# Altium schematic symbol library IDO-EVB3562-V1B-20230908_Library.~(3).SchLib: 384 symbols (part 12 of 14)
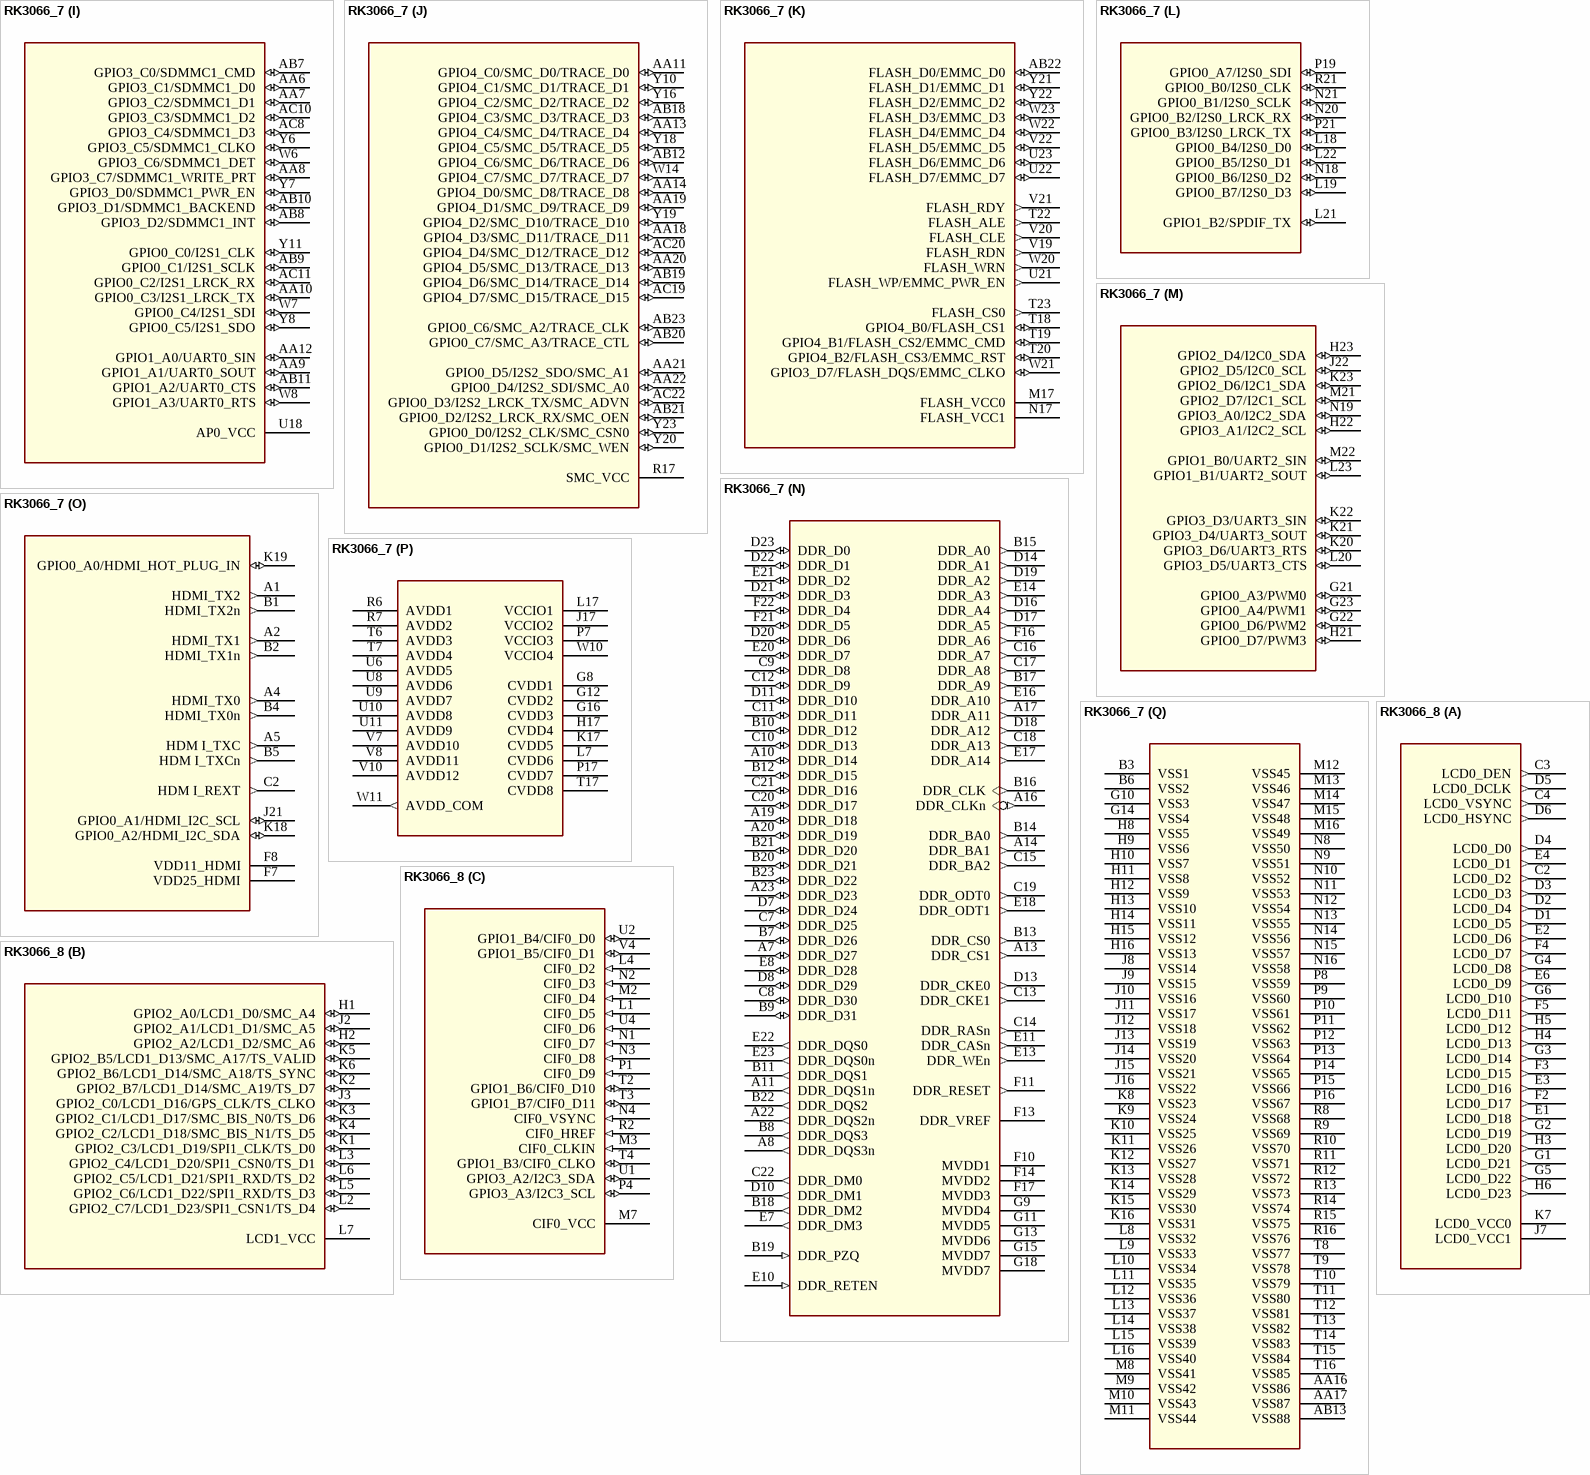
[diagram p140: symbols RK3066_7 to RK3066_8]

## RK3066_7
designator U?
Altium-Right: 160; Altium-Bottom: 130; Altium-Bottom1: 280; Altium-Right2: 180; Altium-Bottom2: 310; Altium-Bottom3: 270; Altium-Right4: 120; Altium-Bottom4: 140; Altium-Bottom5: 230; Altium-Bottom6: 530; Altium-Right7: 150; Altium-Bottom7: 250; Altium-Right8: 110; Altium-Bottom8: 170; Altium-Right9: 100; Altium-Bottom9: 470; Altium-Right10: 80; Altium-Bottom10: 350; Altium-Right11: 200; Altium-Bottom11: 190
footprint BGA453
part A pins: C3 LCD0_DEN (out), C4 LCD0_DCLK (out), C5 LCD0_VSYNC (out), C6 LCD0_HSYNC (out), D1 LCD0_D6 (out), D2 LCD0_D5 (out), D3 LCD0_D4 (out), D4 LCD0_D3 (out), D5 LCD0_D2 (out), D6 LCD0_D1 (out), E1 LCD0_D10 (out), E2 LCD0_D7 (out), E3 LCD0_D9 (out), E4 LCD0_D8 (out), E6 LCD0_D0 (out), F2 LCD0_D13 (out), F3 LCD0_D12 (out), F4 LCD0_D14 (out), F5 LCD0_D11 (out), G1 LCD0_D20 (out), G2 LCD0_D19 (out), G3 LCD0_D18 (out), G4 LCD0_D17 (out), G5 LCD0_D16 (out), G6 LCD0_D15 (out), H1 LCD0_D21 (out), H5 LCD0_D22 (out), H6 LCD0_D23 (out), H7 LCD0_VCC1 (power), J7 LCD0_VCC0 (power)
part B pins: H2 GPIO2_A0/LCD1_D0/SMC_A4 (io), H3 GPIO2_A1/LCD1_D1/SMC_A5 (io), H4 GPIO2_A2/LCD1_D2/SMC_A6 (io), J2 GPIO2_B7/LCD1_D14/SMC_A19/TS_D7 (io), J3 GPIO2_B6/LCD1_D14/SMC_A18/TS_SYNC (io), K1 GPIO2_C2/LCD1_D18/SMC_BIS_N1/TS_D5 (io), K2 GPIO2_C1/LCD1_D17/SMC_BIS_N0/TS_D6 (io), K3 GPIO2_B5/LCD1_D13/SMC_A17/TS_VALID (io), K4 GPIO2_C0/LCD1_D16/GPS_CLK/TS_CLKO (io), K7 LCD1_VCC (power), L1 GPIO2_C5/LCD1_D21/SPI1_RXD/TS_D2 (io), L2 GPIO2_C4/LCD1_D20/SPI1_CSN0/TS_D1 (io), L3 GPIO2_C3/LCD1_D19/SPI1_CLK/TS_D0 (io), L4 GPIO2_C7/LCD1_D23/SPI1_CSN1/TS_D4 (io), M2 GPIO2_C6/LCD1_D22/SPI1_RXD/TS_D3 (io)
part C pins: K5 CIF0_D5 (in), K6 CIF0_D2 (in), L5 CIF0_D9 (in), L6 CIF0_CLKIN (in), M3 CIF0_D8 (in), M7 CIF0_VCC (power), N1 CIF0_D4 (in), N2 CIF0_D3 (in), N3 CIF0_D7 (in), N4 GPIO1_B4/CIF0_D0 (io), N5 GPIO1_B3/CIF0_CLKO (io), N6 GPIO1_B5/CIF0_D1 (io), P1 CIF0_D6 (in), P2 CIF0_VSYNC (in), P3 CIF0_HREF (in), P4 GPIO1_B6/CIF0_D10 (io), P5 GPIO3_A3/I2C3_SCL (io), R2 GPIO3_A2/I2C3_SDA (io), R3 GPIO1_B7/CIF0_D11 (io)
part D pins: N7 CIF1_VCC (power), T1 GPIO1_C5/CIF1_D7/RMII_CRS_DVALID (io), T2 GPIO1_C0/CIF1_D2/RMII_CLKO (io), T3 GPIO1_C2/CIF1_D4/RMII_TXD1 (io), T4 GPIO1_C1/CIF1_D3/RMII_TX_EN (io), T5 GPIO1_C7/CIF1_D9/RMII_RXD0 (io), U1 GPIO1_D2/CIF1_CLKIN (io), U2 GPIO1_C4/CIF1_D6/RMII_RX_ERR (io), U3 GPIO1_C3/CIF1_D5/RMII_TXD0 (io), U4 GPIO1_D0/CIF1_VSYNC/MII_MD (io), U5 GPIO3_A5/I2C4_SCL (io), V2 GPIO1_D7/CIF1_CLKO (io), V3 GPIO1_C6/CIF1_D8/RMII_RXD1 (io), V4 GPIO1_D1/CIF1_HREF/MII_MDCLK (io), V5 GPIO3_A4/I2C4_SDA (io), W4 GPIO1_D6/CIF1_D11 (io)
part E pins: AA2 GPIO6_A4, AA3 GPIO6_A5, AA15 PVCC_3V3 (power), AB1 GPIO6_B0, AB2 GPIO6_B1, AB3 GPIO6_A1, AB4 GPIO6_A7, AB14 XOUT24M (out), AC1 GPIO6_A0, AC2 GPIO6_A3, AC4 GPIO6_A2, AC5 GPIO6_A6, AC13 DDRIO_RET_EN (out), AC14 XIN24M (in), U12 AVSS_APLL (power), U13 AVSS_DPLL (power), U14 AVSS_C/GPLL (power), V11 APLL_1V1 (power), V13 DPLL_1V1 (power), V14 C/GPLL_1V1 (power), V17 EFUSE (in), W13 PVDD_1V1 (power), Y1 CPU_PWROFF (out), Y2 CORE_PWROFF (out), Y3 DDRIO_PWROFF (out), Y4 GPIO6_B2, Y5 GPIO6_B3, Y13 CLKIN_32K (in), Y14 NPOR (in)
part F pins: AB15 HOST_RKELVIN (out), AB16 OTG_DM (io), AB17 HOST_DM (io), AC16 OTG_DP (io), AC17 HOST_DP (io), F19 GPIO0_A6/HOST_DRV (io), F20 TDO (out), G19 TDI/CPR_BYPASS (in), G20 TRSTN (in), H18 TCK/HSSCAN_SHIFT_CLOCK (in), H19 TMS/PLL_BYPASS (io), H20 RECOVER (in), P20 GPIO0_A5/OTG_DRV (io), U15 USBVDD_1V1 (power), U16 USBVDD_2V5 (power), V16 USBVDD_3V3 (power), W1 SARADC_ANI0 (in), W2 SARADC_ANI2 (in), W3 SARADC_ANI1 (in), W16 OTG_RKELVIN (out), W17 OTG_VBUS (in), Y17 OTG_ID (in)
part G pins: AA4 GPIO1_A4/UART1_RX/SPI0_CSN0 (io), AA5 GPIO4_B7/SPI0_CSN1 (io), AB5 GPIO1_A5/UART1_TX/SPI0_CLK (io), AB6 GPIO1_A6/UART1_CTSN/SPI0_RXD (io), AC7 GPIO1_A7/UART1_RTSN/SPI0_TXD (io), W18 AP1_VCC (power)
part H pins: AC23 GPIO3_B6/SDMMC0_DET (io), N22 GPIO3_B4/SDMMC0_D2 (io), N23 GPIO3_B5/SDMMC0_D3 (io), P18 GPIO3_A6/SDMMC0_RSTNO (io), P22 GPIO3_B3/SDMMC0_D1 (io), P23 GPIO3_B7/SDMMC0_WRITE_PRT (io), R22 GPIO3_A7/SDMMC0_PWR_EN (io), T21 GPIO3_B0/SDMMC0_CLKOUT (io), U19 GPIO3_B2/SDMMC0_D0 (io), U20 GPIO3_B1/SDMMC0_CMD (io)
part I pins: AA6 GPIO3_C1/SDMMC1_D0 (io), AA7 GPIO3_C2/SDMMC1_D1 (io), AA8 GPIO3_C7/SDMMC1_WRITE_PRT (io), AA9 GPIO1_A1/UART0_SOUT (io), AA10 GPIO0_C3/I2S1_LRCK_TX (io), AA12 GPIO1_A0/UART0_SIN (io), AB7 GPIO3_C0/SDMMC1_CMD (io), AB8 GPIO3_D2/SDMMC1_INT (io), AB9 GPIO0_C1/I2S1_SCLK (io), AB10 GPIO3_D1/SDMMC1_BACKEND (io), AB11 GPIO1_A2/UART0_CTS (io), AC8 GPIO3_C4/SDMMC1_D3 (io), AC10 GPIO3_C3/SDMMC1_D2 (io), AC11 GPIO0_C2/I2S1_LRCK_RX (io), U18 AP0_VCC (power), W6 GPIO3_C6/SDMMC1_DET (io), W7 GPIO0_C4/I2S1_SDI (io), W8 GPIO1_A3/UART0_RTS (io), Y6 GPIO3_C5/SDMMC1_CLKO (io), Y7 GPIO3_D0/SDMMC1_PWR_EN (io), Y8 GPIO0_C5/I2S1_SDO (io), Y11 GPIO0_C0/I2S1_CLK (io)
part J pins: AA11 GPIO4_C0/SMC_D0/TRACE_D0 (io), AA13 GPIO4_C4/SMC_D4/TRACE_D4 (io), AA14 GPIO4_D0/SMC_D8/TRACE_D8 (io), AA18 GPIO4_D3/SMC_D11/TRACE_D11 (io), AA19 GPIO4_D1/SMC_D9/TRACE_D9 (io), AA20 GPIO4_D5/SMC_D13/TRACE_D13 (io), AA21 GPIO0_D5/I2S2_SDO/SMC_A1 (io), AA22 GPIO0_D4/I2S2_SDI/SMC_A0 (io), AB12 GPIO4_C6/SMC_D6/TRACE_D6 (io), AB18 GPIO4_C3/SMC_D3/TRACE_D3 (io), AB19 GPIO4_D6/SMC_D14/TRACE_D14 (io), AB20 GPIO0_C7/SMC_A3/TRACE_CTL (io), AB21 GPIO0_D2/I2S2_LRCK_RX/SMC_OEN (io), AB23 GPIO0_C6/SMC_A2/TRACE_CLK (io), AC19 GPIO4_D7/SMC_D15/TRACE_D15 (io), AC20 GPIO4_D4/SMC_D12/TRACE_D12 (io), AC22 GPIO0_D3/I2S2_LRCK_TX/SMC_ADVN (io), R17 SMC_VCC (power), W14 GPIO4_C7/SMC_D7/TRACE_D7 (io), Y10 GPIO4_C1/SMC_D1/TRACE_D1 (io), Y16 GPIO4_C2/SMC_D2/TRACE_D2 (io), Y18 GPIO4_C5/SMC_D5/TRACE_D5 (io), Y19 GPIO4_D2/SMC_D10/TRACE_D10 (io), Y20 GPIO0_D1/I2S2_SCLK/SMC_WEN (io), Y23 GPIO0_D0/I2S2_CLK/SMC_CSN0 (io)
part K pins: AB22 FLASH_D0/EMMC_D0 (io), M17 FLASH_VCC0 (power), N17 FLASH_VCC1 (power), T18 GPIO4_B0/FLASH_CS1 (io), T19 GPIO4_B1/FLASH_CS2/EMMC_CMD (io), T20 GPIO4_B2/FLASH_CS3/EMMC_RST (io), T22 FLASH_ALE (out), T23 FLASH_CS0 (out), U21 FLASH_WP/EMMC_PWR_EN (out), U22 FLASH_D7/EMMC_D7 (io), U23 FLASH_D6/EMMC_D6 (io), V19 FLASH_RDN (out), V20 FLASH_CLE (out), V21 FLASH_RDY (out), V22 FLASH_D5/EMMC_D5 (io), W20 FLASH_WRN (out), W21 GPIO3_D7/FLASH_DQS/EMMC_CLKO (io), W22 FLASH_D4/EMMC_D4 (io), W23 FLASH_D3/EMMC_D3 (io), Y21 FLASH_D1/EMMC_D1 (io), Y22 FLASH_D2/EMMC_D2 (io)
part L pins: L18 GPIO0_B4/I2S0_D0 (io), L19 GPIO0_B7/I2S0_D3 (io), L21 GPIO1_B2/SPDIF_TX (io), L22 GPIO0_B5/I2S0_D1 (io), N18 GPIO0_B6/I2S0_D2 (io), N20 GPIO0_B2/I2S0_LRCK_RX (io), N21 GPIO0_B1/I2S0_SCLK (io), P19 GPIO0_A7/I2S0_SDI (io), P21 GPIO0_B3/I2S0_LRCK_TX (io), R21 GPIO0_B0/I2S0_CLK (io)
part M pins: G21 GPIO0_A3/PWM0 (io), G22 GPIO0_D6/PWM2 (io), G23 GPIO0_A4/PWM1 (io), H21 GPIO0_D7/PWM3 (io), H22 GPIO3_A1/I2C2_SCL (io), H23 GPIO2_D4/I2C0_SDA (io), J22 GPIO2_D5/I2C0_SCL (io), K20 GPIO3_D6/UART3_RTS (io), K21 GPIO3_D4/UART3_SOUT (io), K22 GPIO3_D3/UART3_SIN (io), K23 GPIO2_D6/I2C1_SDA (io), L20 GPIO3_D5/UART3_CTS (io), L23 GPIO1_B1/UART2_SOUT (io), M21 GPIO2_D7/I2C1_SCL (io), M22 GPIO1_B0/UART2_SIN (io), N19 GPIO3_A0/I2C2_SDA (io)
part N pins: A7 DDR_D27 (io), A8 DDR_DQS3n (out), A10 DDR_D14 (io), A11 DDR_DQS1n (out), A13 DDR_CS1 (out), A14 DDR_BA1 (out), A16 DDR_CLKn (out), A17 DDR_A11 (out), A19 DDR_D18 (io), A20 DDR_D19 (io), A22 DDR_DQS2n (out), A23 DDR_D23 (io), B7 DDR_D26 (io), B8 DDR_DQS3 (out), B9 DDR_D31 (io), B10 DDR_D12 (io), B11 DDR_DQS1 (out), B12 DDR_D15 (io), B13 DDR_CS0 (out), B14 DDR_BA0 (out), B15 DDR_A0 (out), B16 DDR_CLK (out), B17 DDR_A9 (out), B18 DDR_DM2 (out), B19 DDR_PZQ (in), B20 DDR_D21 (io), B21 DDR_D20 (io), B22 DDR_DQS2 (out), B23 DDR_D22 (io), C7 DDR_D25 (io), C8 DDR_D30 (io), C9 DDR_D8 (io), C10 DDR_D13 (io), C11 DDR_D11 (io), C12 DDR_D9 (io), C13 DDR_CKE1 (out), C14 DDR_RASn (out), C15 DDR_BA2 (out), C16 DDR_A7 (out), C17 DDR_A8 (out), C18 DDR_A13 (out), C19 DDR_ODT0 (out), C20 DDR_D17 (io), C21 DDR_D16 (io), C22 DDR_DM0 (out), D7 DDR_D24 (io), D8 DDR_D29 (io), D10 DDR_DM1 (out), D11 DDR_D10 (io), D13 DDR_CKE0 (out), D14 DDR_A1 (out), D16 DDR_A4 (out), D17 DDR_A5 (out), D18 DDR_A12 (out), D19 DDR_A2 (out), D20 DDR_D6 (io), D21 DDR_D3 (io), D22 DDR_D1 (io), D23 DDR_D0 (io), E7 DDR_DM3 (out), E8 DDR_D28 (io), E10 DDR_RETEN (in), E11 DDR_CASn (out), E13 DDR_WEn (out), E14 DDR_A3 (out), E16 DDR_A10 (out), E17 DDR_A14 (out), E18 DDR_ODT1 (out), E20 DDR_D7 (io), E21 DDR_D2 (io), E22 DDR_DQS0 (out), E23 DDR_DQS0n (out), F10 MVDD1 (power), F11 DDR_RESET (out), F13 DDR_VREF (power), F14 MVDD2 (power), F16 DDR_A6 (out), F17 MVDD3 (power), F21 DDR_D5 (io), F22 DDR_D4 (io), G9 MVDD4 (power), G11 MVDD5 (power), G13 MVDD6 (power), G15 MVDD7 (power), G18 MVDD7 (power)
part O pins: A1 HDMI_TX2 (out), A2 HDMI_TX1 (out), A4 HDMI_TX0 (out), A5 HDM I_TXC (out), B1 HDMI_TX2n (out), B2 HDMI_TX1n (out), B4 HDMI_TX0n (out), B5 HDM I_TXCn (out), C2 HDM I_REXT (out), F7 VDD25_HDMI (power), F8 VDD11_HDMI (power), J21 GPIO0_A1/HDMI_I2C_SCL (io), K18 GPIO0_A2/HDMI_I2C_SDA (io), K19 GPIO0_A0/HDMI_HOT_PLUG_IN (io)
part P pins: G8 CVDD1 (power), G12 CVDD2 (power), G16 CVDD3 (power), H17 CVDD4 (power), J17 VCCIO2 (power), K17 CVDD5 (power), L7 CVDD6 (power), L17 VCCIO1 (power), P7 VCCIO3 (power), P17 CVDD7 (power), R6 AVDD1 (power), R7 AVDD2 (power), T6 AVDD3 (power), T7 AVDD4 (power), T17 CVDD8 (power), U6 AVDD5 (power), U8 AVDD6 (power), U9 AVDD7 (power), U10 AVDD8 (power), U11 AVDD9 (power), V7 AVDD10 (power), V8 AVDD11 (power), V10 AVDD12 (power), W10 VCCIO4 (power), W11 AVDD_COM (out)
part Q pins: AA16 VSS86 (power), AA17 VSS87 (power), AB13 VSS88 (power), B3 VSS1 (power), B6 VSS2 (power), G10 VSS3 (power), G14 VSS4 (power), H8 VSS5 (power), H9 VSS6 (power), H10 VSS7 (power), H11 VSS8 (power), H12 VSS9 (power), H13 VSS10 (power), H14 VSS11 (power), H15 VSS12 (power), H16 VSS13 (power), J8 VSS14 (power), J9 VSS15 (power), J10 VSS16 (power), J11 VSS17 (power), J12 VSS18 (power), J13 VSS19 (power), J14 VSS20 (power), J15 VSS21 (power), J16 VSS22 (power), K8 VSS23 (power), K9 VSS24 (power), K10 VSS25 (power), K11 VSS26 (power), K12 VSS27 (power), K13 VSS28 (power), K14 VSS29 (power), K15 VSS30 (power), K16 VSS31 (power), L8 VSS32 (power), L9 VSS33 (power), L10 VSS34 (power), L11 VSS35 (power), L12 VSS36 (power), L13 VSS37 (power), L14 VSS38 (power), L15 VSS39 (power), L16 VSS40 (power), M8 VSS41 (power), M9 VSS42 (power), M10 VSS43 (power), M11 VSS44 (power), M12 VSS45 (power), M13 VSS46 (power), M14 VSS47 (power), M15 VSS48 (power), M16 VSS49 (power), N8 VSS50 (power), N9 VSS51 (power), N10 VSS52 (power), N11 VSS53 (power), N12 VSS54 (power), N13 VSS55 (power), N14 VSS56 (power), N15 VSS57 (power), N16 VSS58 (power), P8 VSS59 (power), P9 VSS60 (power), P10 VSS61 (power), P11 VSS62 (power), P12 VSS63 (power), P13 VSS64 (power), P14 VSS65 (power), P15 VSS66 (power), P16 VSS67 (power), R8 VSS68 (power), R9 VSS69 (power), R10 VSS70 (power), R11 VSS71 (power), R12 VSS72 (power), R13 VSS73 (power), R14 VSS74 (power), R15 VSS75 (power), R16 VSS76 (power), T8 VSS77 (power), T9 VSS78 (power), T10 VSS79 (power), T11 VSS80 (power), T12 VSS81 (power), T13 VSS82 (power), T14 VSS83 (power), T15 VSS84 (power), T16 VSS85 (power)

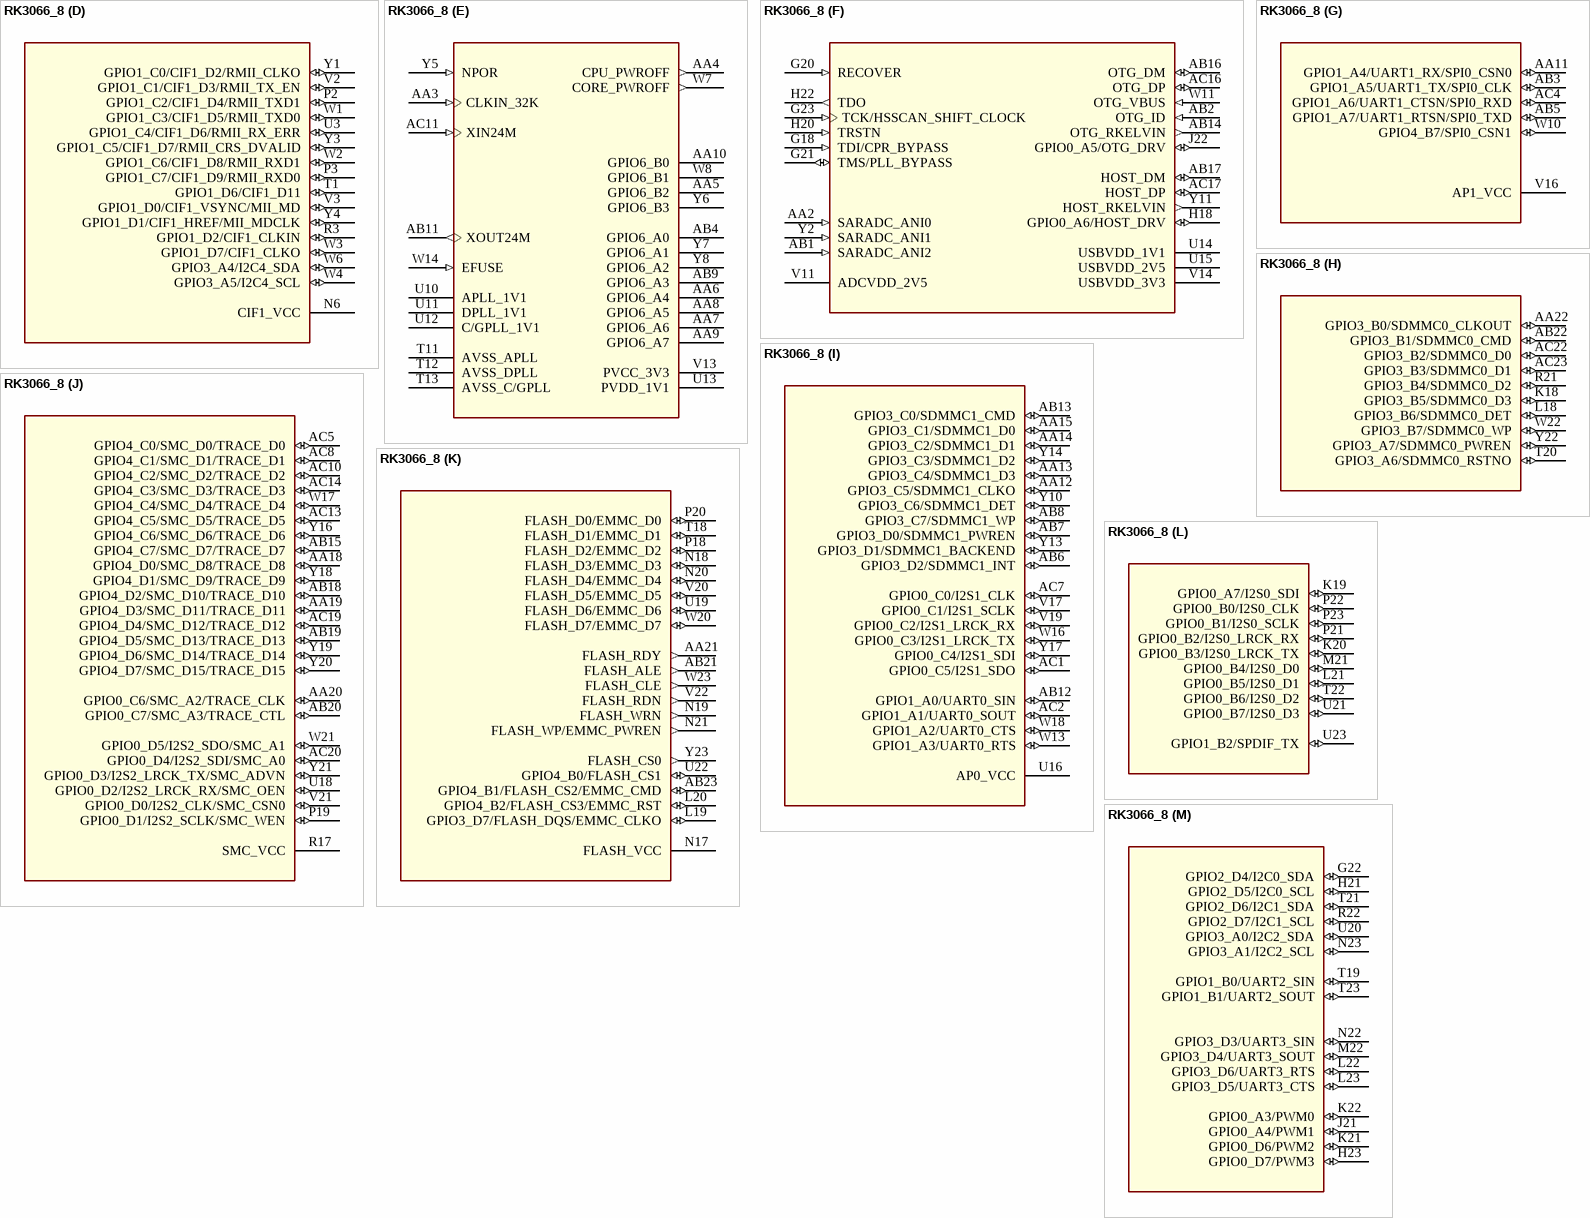
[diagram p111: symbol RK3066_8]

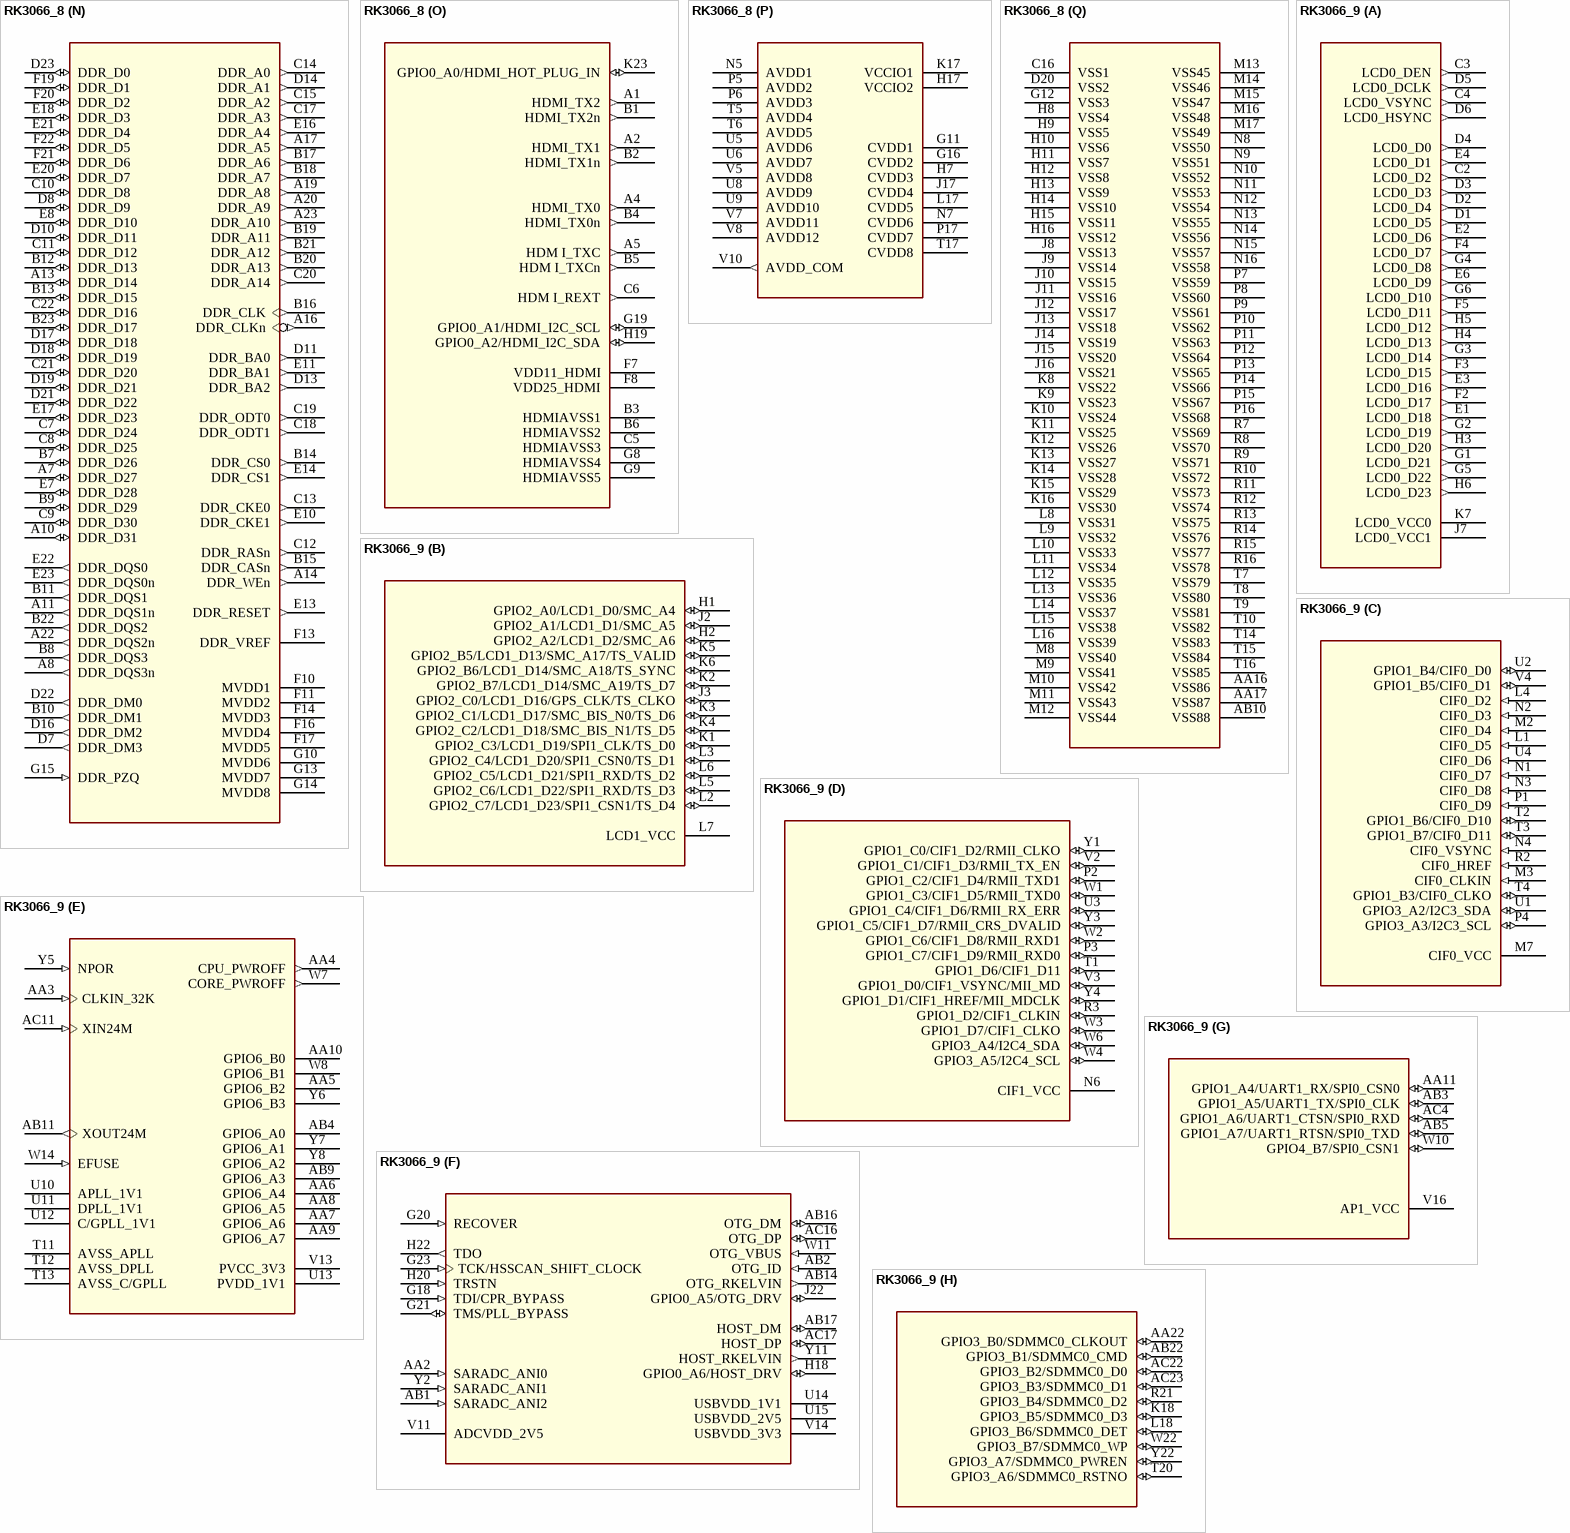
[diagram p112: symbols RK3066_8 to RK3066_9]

## RK3066_8
designator U?
Altium-Right: 160; Altium-Bottom: 280; Altium-Right1: 180; Altium-Bottom1: 310; Altium-Bottom2: 260; Altium-Right3: 120; Altium-Bottom3: 140; Altium-Right4: 130; Altium-Bottom4: 230; Altium-Bottom5: 520; Altium-Right6: 150; Altium-Right7: 110; Altium-Bottom7: 170; Altium-Right8: 100; Altium-Bottom8: 470; Altium-Right9: 80; Altium-Bottom9: 350; Altium-Right10: 200; Altium-Bottom10: 190; Altium-Bottom13: 250
footprint BGA453-19X19
part A pins: C2 LCD0_D2 (out), C3 LCD0_DEN (out), C4 LCD0_VSYNC (out), D1 LCD0_D5 (out), D2 LCD0_D4 (out), D3 LCD0_D3 (out), D4 LCD0_D0 (out), D5 LCD0_DCLK (out), D6 LCD0_HSYNC (out), E1 LCD0_D18 (out), E2 LCD0_D6 (out), E3 LCD0_D16 (out), E4 LCD0_D1 (out), E6 LCD0_D9 (out), F2 LCD0_D17 (out), F3 LCD0_D15 (out), F4 LCD0_D7 (out), F5 LCD0_D11 (out), G1 LCD0_D21 (out), G2 LCD0_D19 (out), G3 LCD0_D14 (out), G4 LCD0_D8 (out), G5 LCD0_D22 (out), G6 LCD0_D10 (out), H3 LCD0_D20 (out), H4 LCD0_D13 (out), H5 LCD0_D12 (out), H6 LCD0_D23 (out), J7 LCD0_VCC1 (power), K7 LCD0_VCC0 (power)
part B pins: H1 GPIO2_A0/LCD1_D0/SMC_A4 (io), H2 GPIO2_A2/LCD1_D2/SMC_A6 (io), J2 GPIO2_A1/LCD1_D1/SMC_A5 (io), J3 GPIO2_C0/LCD1_D16/GPS_CLK/TS_CLKO (io), K1 GPIO2_C3/LCD1_D19/SPI1_CLK/TS_D0 (io), K2 GPIO2_B7/LCD1_D14/SMC_A19/TS_D7 (io), K3 GPIO2_C1/LCD1_D17/SMC_BIS_N0/TS_D6 (io), K4 GPIO2_C2/LCD1_D18/SMC_BIS_N1/TS_D5 (io), K5 GPIO2_B5/LCD1_D13/SMC_A17/TS_VALID (io), K6 GPIO2_B6/LCD1_D14/SMC_A18/TS_SYNC (io), L2 GPIO2_C7/LCD1_D23/SPI1_CSN1/TS_D4 (io), L3 GPIO2_C4/LCD1_D20/SPI1_CSN0/TS_D1 (io), L5 GPIO2_C6/LCD1_D22/SPI1_RXD/TS_D3 (io), L6 GPIO2_C5/LCD1_D21/SPI1_RXD/TS_D2 (io), L7 LCD1_VCC (power)
part C pins: L1 CIF0_D5 (in), L4 CIF0_D2 (in), M2 CIF0_D4 (in), M3 CIF0_CLKIN (in), M7 CIF0_VCC (power), N1 CIF0_D7 (in), N2 CIF0_D3 (in), N3 CIF0_D8 (in), N4 CIF0_VSYNC (in), P1 CIF0_D9 (in), P4 GPIO3_A3/I2C3_SCL (io), R2 CIF0_HREF (in), T2 GPIO1_B6/CIF0_D10 (io), T3 GPIO1_B7/CIF0_D11 (io), T4 GPIO1_B3/CIF0_CLKO (io), U1 GPIO3_A2/I2C3_SDA (io), U2 GPIO1_B4/CIF0_D0 (io), U4 CIF0_D6 (in), V4 GPIO1_B5/CIF0_D1 (io)
part D pins: N6 CIF1_VCC (power), P2 GPIO1_C2/CIF1_D4/RMII_TXD1 (io), P3 GPIO1_C7/CIF1_D9/RMII_RXD0 (io), R3 GPIO1_D2/CIF1_CLKIN (io), T1 GPIO1_D6/CIF1_D11 (io), U3 GPIO1_C4/CIF1_D6/RMII_RX_ERR (io), V2 GPIO1_C1/CIF1_D3/RMII_TX_EN (io), V3 GPIO1_D0/CIF1_VSYNC/MII_MD (io), W1 GPIO1_C3/CIF1_D5/RMII_TXD0 (io), W2 GPIO1_C6/CIF1_D8/RMII_RXD1 (io), W3 GPIO1_D7/CIF1_CLKO (io), W4 GPIO3_A5/I2C4_SCL (io), W6 GPIO3_A4/I2C4_SDA (io), Y1 GPIO1_C0/CIF1_D2/RMII_CLKO (io), Y3 GPIO1_C5/CIF1_D7/RMII_CRS_DVALID (io), Y4 GPIO1_D1/CIF1_HREF/MII_MDCLK (io)
part E pins: AA3 CLKIN_32K (in), AA4 CPU_PWROFF (out), AA5 GPIO6_B2, AA6 GPIO6_A4, AA7 GPIO6_A6, AA8 GPIO6_A5, AA9 GPIO6_A7, AA10 GPIO6_B0, AB4 GPIO6_A0, AB9 GPIO6_A3, AB11 XOUT24M (out), AC11 XIN24M (in), T11 AVSS_APLL (power), T12 AVSS_DPLL (power), T13 AVSS_C/GPLL (power), U10 APLL_1V1 (power), U11 DPLL_1V1 (power), U12 C/GPLL_1V1 (power), U13 PVDD_1V1 (power), V13 PVCC_3V3 (power), W7 CORE_PWROFF (out), W8 GPIO6_B1, W14 EFUSE (in), Y5 NPOR (in), Y6 GPIO6_B3, Y7 GPIO6_A1, Y8 GPIO6_A2
part F pins: AA2 SARADC_ANI0 (in), AB1 SARADC_ANI2 (in), AB2 OTG_ID (in), AB14 OTG_RKELVIN (out), AB16 OTG_DM (io), AB17 HOST_DM (io), AC16 OTG_DP (io), AC17 HOST_DP (io), G18 TDI/CPR_BYPASS (in), G20 RECOVER (in), G21 TMS/PLL_BYPASS (io), G23 TCK/HSSCAN_SHIFT_CLOCK (in), H18 GPIO0_A6/HOST_DRV (io), H20 TRSTN (in), H22 TDO (out), J22 GPIO0_A5/OTG_DRV (io), U14 USBVDD_1V1 (power), U15 USBVDD_2V5 (power), V11 ADCVDD_2V5 (power), V14 USBVDD_3V3 (power), W11 OTG_VBUS (in), Y2 SARADC_ANI1 (in), Y11 HOST_RKELVIN (out)
part G pins: AA11 GPIO1_A4/UART1_RX/SPI0_CSN0 (io), AB3 GPIO1_A5/UART1_TX/SPI0_CLK (io), AB5 GPIO1_A7/UART1_RTSN/SPI0_TXD (io), AC4 GPIO1_A6/UART1_CTSN/SPI0_RXD (io), V16 AP1_VCC (power), W10 GPIO4_B7/SPI0_CSN1 (io)
part H pins: AA22 GPIO3_B0/SDMMC0_CLKOUT (io), AB22 GPIO3_B1/SDMMC0_CMD (io), AC22 GPIO3_B2/SDMMC0_D0 (io), AC23 GPIO3_B3/SDMMC0_D1 (io), K18 GPIO3_B5/SDMMC0_D3 (io), L18 GPIO3_B6/SDMMC0_DET (io), R21 GPIO3_B4/SDMMC0_D2 (io), T20 GPIO3_A6/SDMMC0_RSTNO (io), W22 GPIO3_B7/SDMMC0_WP (io), Y22 GPIO3_A7/SDMMC0_PWREN (io)
part I pins: AA12 GPIO3_C5/SDMMC1_CLKO (io), AA13 GPIO3_C4/SDMMC1_D3 (io), AA14 GPIO3_C2/SDMMC1_D1 (io), AA15 GPIO3_C1/SDMMC1_D0 (io), AB6 GPIO3_D2/SDMMC1_INT (io), AB7 GPIO3_D0/SDMMC1_PWREN (io), AB8 GPIO3_C7/SDMMC1_WP (io), AB12 GPIO1_A0/UART0_SIN (io), AB13 GPIO3_C0/SDMMC1_CMD (io), AC1 GPIO0_C5/I2S1_SDO (io), AC2 GPIO1_A1/UART0_SOUT (io), AC7 GPIO0_C0/I2S1_CLK (io), U16 AP0_VCC (power), V17 GPIO0_C1/I2S1_SCLK (io), V19 GPIO0_C2/I2S1_LRCK_RX (io), W13 GPIO1_A3/UART0_RTS (io), W16 GPIO0_C3/I2S1_LRCK_TX (io), W18 GPIO1_A2/UART0_CTS (io), Y10 GPIO3_C6/SDMMC1_DET (io), Y13 GPIO3_D1/SDMMC1_BACKEND (io), Y14 GPIO3_C3/SDMMC1_D2 (io), Y17 GPIO0_C4/I2S1_SDI (io)
part J pins: AA18 GPIO4_D0/SMC_D8/TRACE_D8 (io), AA19 GPIO4_D3/SMC_D11/TRACE_D11 (io), AA20 GPIO0_C6/SMC_A2/TRACE_CLK (io), AB15 GPIO4_C7/SMC_D7/TRACE_D7 (io), AB18 GPIO4_D2/SMC_D10/TRACE_D10 (io), AB19 GPIO4_D5/SMC_D13/TRACE_D13 (io), AB20 GPIO0_C7/SMC_A3/TRACE_CTL (io), AC5 GPIO4_C0/SMC_D0/TRACE_D0 (io), AC8 GPIO4_C1/SMC_D1/TRACE_D1 (io), AC10 GPIO4_C2/SMC_D2/TRACE_D2 (io), AC13 GPIO4_C5/SMC_D5/TRACE_D5 (io), AC14 GPIO4_C3/SMC_D3/TRACE_D3 (io), AC19 GPIO4_D4/SMC_D12/TRACE_D12 (io), AC20 GPIO0_D4/I2S2_SDI/SMC_A0 (io), P19 GPIO0_D1/I2S2_SCLK/SMC_WEN (io), R17 SMC_VCC (power), U18 GPIO0_D2/I2S2_LRCK_RX/SMC_OEN (io), V21 GPIO0_D0/I2S2_CLK/SMC_CSN0 (io), W17 GPIO4_C4/SMC_D4/TRACE_D4 (io), W21 GPIO0_D5/I2S2_SDO/SMC_A1 (io), Y16 GPIO4_C6/SMC_D6/TRACE_D6 (io), Y18 GPIO4_D1/SMC_D9/TRACE_D9 (io), Y19 GPIO4_D6/SMC_D14/TRACE_D14 (io), Y20 GPIO4_D7/SMC_D15/TRACE_D15 (io), Y21 GPIO0_D3/I2S2_LRCK_TX/SMC_ADVN (io)
part K pins: AA21 FLASH_RDY (out), AB21 FLASH_ALE (out), AB23 GPIO4_B1/FLASH_CS2/EMMC_CMD (io), L19 GPIO3_D7/FLASH_DQS/EMMC_CLKO (io), L20 GPIO4_B2/FLASH_CS3/EMMC_RST (io), N17 FLASH_VCC (power), N18 FLASH_D3/EMMC_D3 (io), N19 FLASH_WRN (out), N20 FLASH_D4/EMMC_D4 (io), N21 FLASH_WP/EMMC_PWREN (out), P18 FLASH_D2/EMMC_D2 (io), P20 FLASH_D0/EMMC_D0 (io), T18 FLASH_D1/EMMC_D1 (io), U19 FLASH_D6/EMMC_D6 (io), U22 GPIO4_B0/FLASH_CS1 (io), V20 FLASH_D5/EMMC_D5 (io), V22 FLASH_RDN (out), W20 FLASH_D7/EMMC_D7 (io), W23 FLASH_CLE (out), Y23 FLASH_CS0 (out)
part L pins: K19 GPIO0_A7/I2S0_SDI (io), K20 GPIO0_B3/I2S0_LRCK_TX (io), L21 GPIO0_B5/I2S0_D1 (io), M21 GPIO0_B4/I2S0_D0 (io), P21 GPIO0_B2/I2S0_LRCK_RX (io), P22 GPIO0_B0/I2S0_CLK (io), P23 GPIO0_B1/I2S0_SCLK (io), T22 GPIO0_B6/I2S0_D2 (io), U21 GPIO0_B7/I2S0_D3 (io), U23 GPIO1_B2/SPDIF_TX (io)
part M pins: G22 GPIO2_D4/I2C0_SDA (io), H21 GPIO2_D5/I2C0_SCL (io), H23 GPIO0_D7/PWM3 (io), J21 GPIO0_A4/PWM1 (io), K21 GPIO0_D6/PWM2 (io), K22 GPIO0_A3/PWM0 (io), L22 GPIO3_D6/UART3_RTS (io), L23 GPIO3_D5/UART3_CTS (io), M22 GPIO3_D4/UART3_SOUT (io), N22 GPIO3_D3/UART3_SIN (io), N23 GPIO3_A1/I2C2_SCL (io), R22 GPIO2_D7/I2C1_SCL (io), T19 GPIO1_B0/UART2_SIN (io), T21 GPIO2_D6/I2C1_SDA (io), T23 GPIO1_B1/UART2_SOUT (io), U20 GPIO3_A0/I2C2_SDA (io)
part N pins: A7 DDR_D27 (io), A8 DDR_DQS3n (out), A10 DDR_D31 (io), A11 DDR_DQS1n (out), A13 DDR_D14 (io), A14 DDR_WEn (out), A16 DDR_CLKn (out), A17 DDR_A5 (out), A19 DDR_A8 (out), A20 DDR_A9 (out), A22 DDR_DQS2n (out), A23 DDR_A10 (out), B7 DDR_D26 (io), B8 DDR_DQS3 (out), B9 DDR_D29 (io), B10 DDR_DM1 (out), B11 DDR_DQS1 (out), B12 DDR_D13 (io), B13 DDR_D15 (io), B14 DDR_CS0 (out), B15 DDR_CASn (out), B16 DDR_CLK (out), B17 DDR_A6 (out), B18 DDR_A7 (out), B19 DDR_A11 (out), B20 DDR_A13 (out), B21 DDR_A12 (out), B22 DDR_DQS2 (out), B23 DDR_D17 (io), C7 DDR_D24 (io), C8 DDR_D25 (io), C9 DDR_D30 (io), C10 DDR_D8 (io), C11 DDR_D12 (io), C12 DDR_RASn (out), C13 DDR_CKE0 (out), C14 DDR_A0 (out), C15 DDR_A2 (out), C17 DDR_A3 (out), C18 DDR_ODT1 (out), C19 DDR_ODT0 (out), C20 DDR_A14 (out), C21 DDR_D20 (io), C22 DDR_D16 (io), D7 DDR_DM3 (out), D8 DDR_D9 (io), D10 DDR_D11 (io), D11 DDR_BA0 (out), D13 DDR_BA2 (out), D14 DDR_A1 (out), D16 DDR_DM2 (out), D17 DDR_D18 (io), D18 DDR_D19 (io), D19 DDR_D21 (io), D21 DDR_D22 (io), D22 DDR_DM0 (out), D23 DDR_D0 (io), E7 DDR_D28 (io), E8 DDR_D10 (io), E10 DDR_CKE1 (out), E11 DDR_BA1 (out), E13 DDR_RESET (out), E14 DDR_CS1 (out), E16 DDR_A4 (out), E17 DDR_D23 (io), E18 DDR_D3 (io), E20 DDR_D7 (io), E21 DDR_D4 (io), E22 DDR_DQS0 (out), E23 DDR_DQS0n (out), F10 MVDD1 (power), F11 MVDD2 (power), F13 DDR_VREF (power), F14 MVDD3 (power), F16 MVDD4 (power), F17 MVDD5 (power), F19 DDR_D1 (io), F20 DDR_D2 (io), F21 DDR_D6 (io), F22 DDR_D5 (io), G10 MVDD6 (power), G13 MVDD7 (power), G14 MVDD8 (power), G15 DDR_PZQ (in)
part O pins: A1 HDMI_TX2 (out), A2 HDMI_TX1 (out), A4 HDMI_TX0 (out), A5 HDM I_TXC (out), B1 HDMI_TX2n (out), B2 HDMI_TX1n (out), B3 HDMIAVSS1 (power), B4 HDMI_TX0n (out), B5 HDM I_TXCn (out), B6 HDMIAVSS2 (power), C5 HDMIAVSS3 (power), C6 HDM I_REXT (out), F7 VDD11_HDMI (power), F8 VDD25_HDMI (power), G8 HDMIAVSS4 (power), G9 HDMIAVSS5 (power), G19 GPIO0_A1/HDMI_I2C_SCL (io), H19 GPIO0_A2/HDMI_I2C_SDA (io), K23 GPIO0_A0/HDMI_HOT_PLUG_IN (io)
part P pins: G11 CVDD1 (power), G16 CVDD2 (power), H7 CVDD3 (power), H17 VCCIO2 (power), J17 CVDD4 (power), K17 VCCIO1 (power), L17 CVDD5 (power), N5 AVDD1 (power), N7 CVDD6 (power), P5 AVDD2 (power), P6 AVDD3 (power), P17 CVDD7 (power), T5 AVDD4 (power), T6 AVDD5 (power), T17 CVDD8 (power), U5 AVDD6 (power), U6 AVDD7 (power), U8 AVDD9 (power), U9 AVDD10 (power), V5 AVDD8 (power), V7 AVDD11 (power), V8 AVDD12 (power), V10 AVDD_COM (out)
part Q pins: AA16 VSS86 (power), AA17 VSS87 (power), AB10 VSS88 (power), C16 VSS1 (power), D20 VSS2 (power), G12 VSS3 (power), H8 VSS4 (power), H9 VSS5 (power), H10 VSS6 (power), H11 VSS7 (power), H12 VSS8 (power), H13 VSS9 (power), H14 VSS10 (power), H15 VSS11 (power), H16 VSS12 (power), J8 VSS13 (power), J9 VSS14 (power), J10 VSS15 (power), J11 VSS16 (power), J12 VSS17 (power), J13 VSS18 (power), J14 VSS19 (power), J15 VSS20 (power), J16 VSS21 (power), K8 VSS22 (power), K9 VSS23 (power), K10 VSS24 (power), K11 VSS25 (power), K12 VSS26 (power), K13 VSS27 (power), K14 VSS28 (power), K15 VSS29 (power), K16 VSS30 (power), L8 VSS31 (power), L9 VSS32 (power), L10 VSS33 (power), L11 VSS34 (power), L12 VSS35 (power), L13 VSS36 (power), L14 VSS37 (power), L15 VSS38 (power), L16 VSS39 (power), M8 VSS40 (power), M9 VSS41 (power), M10 VSS42 (power), M11 VSS43 (power), M12 VSS44 (power), M13 VSS45 (power), M14 VSS46 (power), M15 VSS47 (power), M16 VSS48 (power), M17 VSS49 (power), N8 VSS50 (power), N9 VSS51 (power), N10 VSS52 (power), N11 VSS53 (power), N12 VSS54 (power), N13 VSS55 (power), N14 VSS56 (power), N15 VSS57 (power), N16 VSS58 (power), P7 VSS59 (power), P8 VSS60 (power), P9 VSS61 (power), P10 VSS62 (power), P11 VSS63 (power), P12 VSS64 (power), P13 VSS65 (power), P14 VSS66 (power), P15 VSS67 (power), P16 VSS68 (power), R7 VSS69 (power), R8 VSS70 (power), R9 VSS71 (power), R10 VSS72 (power), R11 VSS73 (power), R12 VSS74 (power), R13 VSS75 (power), R14 VSS76 (power), R15 VSS77 (power), R16 VSS78 (power), T7 VSS79 (power), T8 VSS80 (power), T9 VSS81 (power), T10 VSS82 (power), T14 VSS83 (power), T15 VSS84 (power), T16 VSS85 (power)

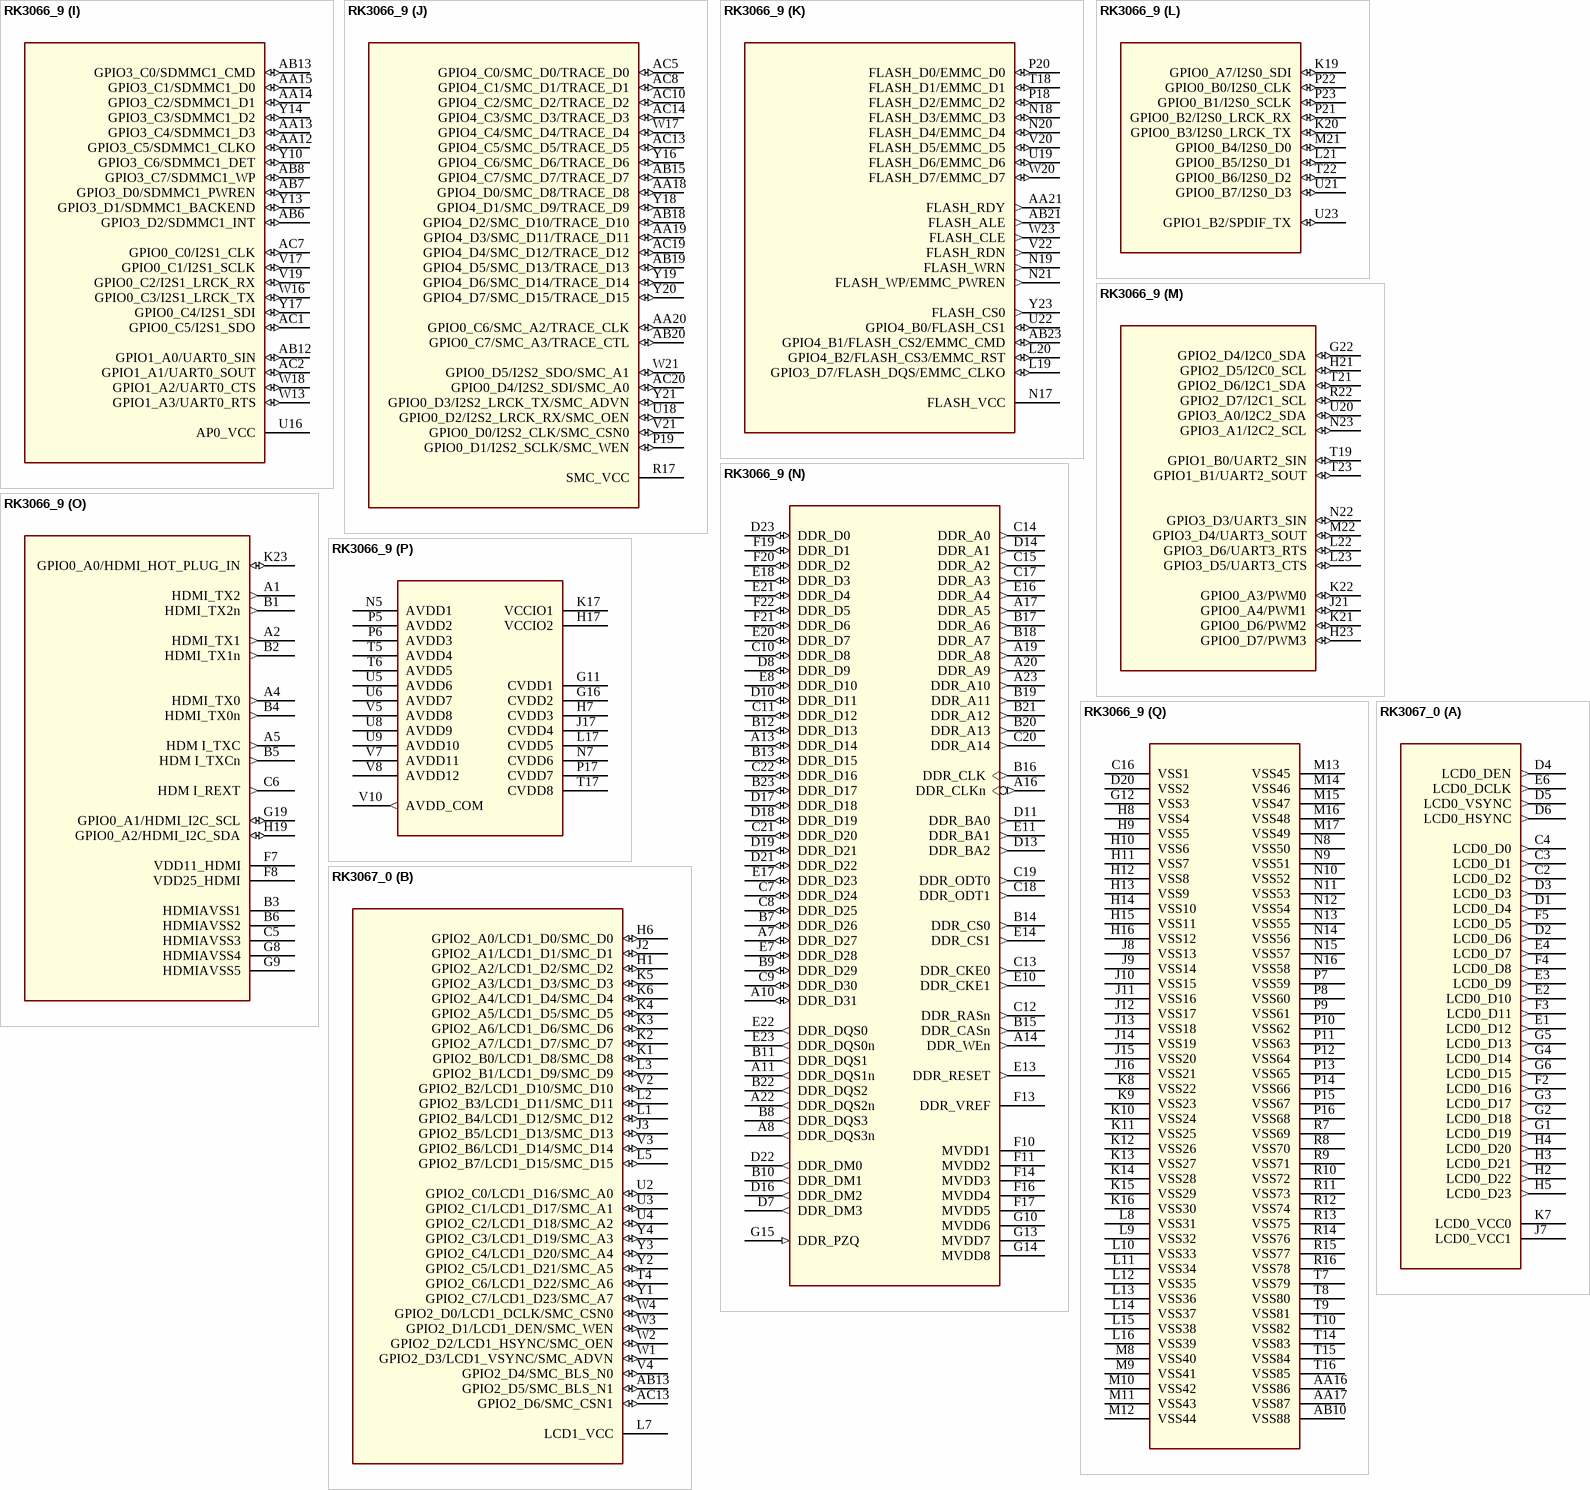
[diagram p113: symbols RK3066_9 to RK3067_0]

## RK3066_9
designator U?
Altium-Right: 180; Altium-Bottom: 310; Altium-Bottom1: 260; Altium-Right2: 120; Altium-Bottom2: 140; Altium-Right3: 130; Altium-Bottom3: 230; Altium-Bottom4: 520; Altium-Right5: 150; Altium-Right6: 110; Altium-Bottom6: 170; Altium-Right7: 100; Altium-Bottom7: 470; Altium-Right8: 80; Altium-Bottom8: 350; Altium-Right9: 200; Altium-Bottom9: 190; Altium-Bottom12: 250; Altium-Right14: 160; Altium-Bottom16: 280
footprint BGA453-19X19
part A pins: C2 LCD0_D2 (out), C3 LCD0_DEN (out), C4 LCD0_VSYNC (out), D1 LCD0_D5 (out), D2 LCD0_D4 (out), D3 LCD0_D3 (out), D4 LCD0_D0 (out), D5 LCD0_DCLK (out), D6 LCD0_HSYNC (out), E1 LCD0_D18 (out), E2 LCD0_D6 (out), E3 LCD0_D16 (out), E4 LCD0_D1 (out), E6 LCD0_D9 (out), F2 LCD0_D17 (out), F3 LCD0_D15 (out), F4 LCD0_D7 (out), F5 LCD0_D11 (out), G1 LCD0_D21 (out), G2 LCD0_D19 (out), G3 LCD0_D14 (out), G4 LCD0_D8 (out), G5 LCD0_D22 (out), G6 LCD0_D10 (out), H3 LCD0_D20 (out), H4 LCD0_D13 (out), H5 LCD0_D12 (out), H6 LCD0_D23 (out), J7 LCD0_VCC1 (power), K7 LCD0_VCC0 (power)
part B pins: H1 GPIO2_A0/LCD1_D0/SMC_A4 (io), H2 GPIO2_A2/LCD1_D2/SMC_A6 (io), J2 GPIO2_A1/LCD1_D1/SMC_A5 (io), J3 GPIO2_C0/LCD1_D16/GPS_CLK/TS_CLKO (io), K1 GPIO2_C3/LCD1_D19/SPI1_CLK/TS_D0 (io), K2 GPIO2_B7/LCD1_D14/SMC_A19/TS_D7 (io), K3 GPIO2_C1/LCD1_D17/SMC_BIS_N0/TS_D6 (io), K4 GPIO2_C2/LCD1_D18/SMC_BIS_N1/TS_D5 (io), K5 GPIO2_B5/LCD1_D13/SMC_A17/TS_VALID (io), K6 GPIO2_B6/LCD1_D14/SMC_A18/TS_SYNC (io), L2 GPIO2_C7/LCD1_D23/SPI1_CSN1/TS_D4 (io), L3 GPIO2_C4/LCD1_D20/SPI1_CSN0/TS_D1 (io), L5 GPIO2_C6/LCD1_D22/SPI1_RXD/TS_D3 (io), L6 GPIO2_C5/LCD1_D21/SPI1_RXD/TS_D2 (io), L7 LCD1_VCC (power)
part C pins: L1 CIF0_D5 (in), L4 CIF0_D2 (in), M2 CIF0_D4 (in), M3 CIF0_CLKIN (in), M7 CIF0_VCC (power), N1 CIF0_D7 (in), N2 CIF0_D3 (in), N3 CIF0_D8 (in), N4 CIF0_VSYNC (in), P1 CIF0_D9 (in), P4 GPIO3_A3/I2C3_SCL (io), R2 CIF0_HREF (in), T2 GPIO1_B6/CIF0_D10 (io), T3 GPIO1_B7/CIF0_D11 (io), T4 GPIO1_B3/CIF0_CLKO (io), U1 GPIO3_A2/I2C3_SDA (io), U2 GPIO1_B4/CIF0_D0 (io), U4 CIF0_D6 (in), V4 GPIO1_B5/CIF0_D1 (io)
part D pins: N6 CIF1_VCC (power), P2 GPIO1_C2/CIF1_D4/RMII_TXD1 (io), P3 GPIO1_C7/CIF1_D9/RMII_RXD0 (io), R3 GPIO1_D2/CIF1_CLKIN (io), T1 GPIO1_D6/CIF1_D11 (io), U3 GPIO1_C4/CIF1_D6/RMII_RX_ERR (io), V2 GPIO1_C1/CIF1_D3/RMII_TX_EN (io), V3 GPIO1_D0/CIF1_VSYNC/MII_MD (io), W1 GPIO1_C3/CIF1_D5/RMII_TXD0 (io), W2 GPIO1_C6/CIF1_D8/RMII_RXD1 (io), W3 GPIO1_D7/CIF1_CLKO (io), W4 GPIO3_A5/I2C4_SCL (io), W6 GPIO3_A4/I2C4_SDA (io), Y1 GPIO1_C0/CIF1_D2/RMII_CLKO (io), Y3 GPIO1_C5/CIF1_D7/RMII_CRS_DVALID (io), Y4 GPIO1_D1/CIF1_HREF/MII_MDCLK (io)
part E pins: AA3 CLKIN_32K (in), AA4 CPU_PWROFF (out), AA5 GPIO6_B2, AA6 GPIO6_A4, AA7 GPIO6_A6, AA8 GPIO6_A5, AA9 GPIO6_A7, AA10 GPIO6_B0, AB4 GPIO6_A0, AB9 GPIO6_A3, AB11 XOUT24M (out), AC11 XIN24M (in), T11 AVSS_APLL (power), T12 AVSS_DPLL (power), T13 AVSS_C/GPLL (power), U10 APLL_1V1 (power), U11 DPLL_1V1 (power), U12 C/GPLL_1V1 (power), U13 PVDD_1V1 (power), V13 PVCC_3V3 (power), W7 CORE_PWROFF (out), W8 GPIO6_B1, W14 EFUSE (in), Y5 NPOR (in), Y6 GPIO6_B3, Y7 GPIO6_A1, Y8 GPIO6_A2
part F pins: AA2 SARADC_ANI0 (in), AB1 SARADC_ANI2 (in), AB2 OTG_ID (in), AB14 OTG_RKELVIN (out), AB16 OTG_DM (io), AB17 HOST_DM (io), AC16 OTG_DP (io), AC17 HOST_DP (io), G18 TDI/CPR_BYPASS (in), G20 RECOVER (in), G21 TMS/PLL_BYPASS (io), G23 TCK/HSSCAN_SHIFT_CLOCK (in), H18 GPIO0_A6/HOST_DRV (io), H20 TRSTN (in), H22 TDO (out), J22 GPIO0_A5/OTG_DRV (io), U14 USBVDD_1V1 (power), U15 USBVDD_2V5 (power), V11 ADCVDD_2V5 (power), V14 USBVDD_3V3 (power), W11 OTG_VBUS (in), Y2 SARADC_ANI1 (in), Y11 HOST_RKELVIN (out)
part G pins: AA11 GPIO1_A4/UART1_RX/SPI0_CSN0 (io), AB3 GPIO1_A5/UART1_TX/SPI0_CLK (io), AB5 GPIO1_A7/UART1_RTSN/SPI0_TXD (io), AC4 GPIO1_A6/UART1_CTSN/SPI0_RXD (io), V16 AP1_VCC (power), W10 GPIO4_B7/SPI0_CSN1 (io)
part H pins: AA22 GPIO3_B0/SDMMC0_CLKOUT (io), AB22 GPIO3_B1/SDMMC0_CMD (io), AC22 GPIO3_B2/SDMMC0_D0 (io), AC23 GPIO3_B3/SDMMC0_D1 (io), K18 GPIO3_B5/SDMMC0_D3 (io), L18 GPIO3_B6/SDMMC0_DET (io), R21 GPIO3_B4/SDMMC0_D2 (io), T20 GPIO3_A6/SDMMC0_RSTNO (io), W22 GPIO3_B7/SDMMC0_WP (io), Y22 GPIO3_A7/SDMMC0_PWREN (io)
part I pins: AA12 GPIO3_C5/SDMMC1_CLKO (io), AA13 GPIO3_C4/SDMMC1_D3 (io), AA14 GPIO3_C2/SDMMC1_D1 (io), AA15 GPIO3_C1/SDMMC1_D0 (io), AB6 GPIO3_D2/SDMMC1_INT (io), AB7 GPIO3_D0/SDMMC1_PWREN (io), AB8 GPIO3_C7/SDMMC1_WP (io), AB12 GPIO1_A0/UART0_SIN (io), AB13 GPIO3_C0/SDMMC1_CMD (io), AC1 GPIO0_C5/I2S1_SDO (io), AC2 GPIO1_A1/UART0_SOUT (io), AC7 GPIO0_C0/I2S1_CLK (io), U16 AP0_VCC (power), V17 GPIO0_C1/I2S1_SCLK (io), V19 GPIO0_C2/I2S1_LRCK_RX (io), W13 GPIO1_A3/UART0_RTS (io), W16 GPIO0_C3/I2S1_LRCK_TX (io), W18 GPIO1_A2/UART0_CTS (io), Y10 GPIO3_C6/SDMMC1_DET (io), Y13 GPIO3_D1/SDMMC1_BACKEND (io), Y14 GPIO3_C3/SDMMC1_D2 (io), Y17 GPIO0_C4/I2S1_SDI (io)
part J pins: AA18 GPIO4_D0/SMC_D8/TRACE_D8 (io), AA19 GPIO4_D3/SMC_D11/TRACE_D11 (io), AA20 GPIO0_C6/SMC_A2/TRACE_CLK (io), AB15 GPIO4_C7/SMC_D7/TRACE_D7 (io), AB18 GPIO4_D2/SMC_D10/TRACE_D10 (io), AB19 GPIO4_D5/SMC_D13/TRACE_D13 (io), AB20 GPIO0_C7/SMC_A3/TRACE_CTL (io), AC5 GPIO4_C0/SMC_D0/TRACE_D0 (io), AC8 GPIO4_C1/SMC_D1/TRACE_D1 (io), AC10 GPIO4_C2/SMC_D2/TRACE_D2 (io), AC13 GPIO4_C5/SMC_D5/TRACE_D5 (io), AC14 GPIO4_C3/SMC_D3/TRACE_D3 (io), AC19 GPIO4_D4/SMC_D12/TRACE_D12 (io), AC20 GPIO0_D4/I2S2_SDI/SMC_A0 (io), P19 GPIO0_D1/I2S2_SCLK/SMC_WEN (io), R17 SMC_VCC (power), U18 GPIO0_D2/I2S2_LRCK_RX/SMC_OEN (io), V21 GPIO0_D0/I2S2_CLK/SMC_CSN0 (io), W17 GPIO4_C4/SMC_D4/TRACE_D4 (io), W21 GPIO0_D5/I2S2_SDO/SMC_A1 (io), Y16 GPIO4_C6/SMC_D6/TRACE_D6 (io), Y18 GPIO4_D1/SMC_D9/TRACE_D9 (io), Y19 GPIO4_D6/SMC_D14/TRACE_D14 (io), Y20 GPIO4_D7/SMC_D15/TRACE_D15 (io), Y21 GPIO0_D3/I2S2_LRCK_TX/SMC_ADVN (io)
part K pins: AA21 FLASH_RDY (out), AB21 FLASH_ALE (out), AB23 GPIO4_B1/FLASH_CS2/EMMC_CMD (io), L19 GPIO3_D7/FLASH_DQS/EMMC_CLKO (io), L20 GPIO4_B2/FLASH_CS3/EMMC_RST (io), N17 FLASH_VCC (power), N18 FLASH_D3/EMMC_D3 (io), N19 FLASH_WRN (out), N20 FLASH_D4/EMMC_D4 (io), N21 FLASH_WP/EMMC_PWREN (out), P18 FLASH_D2/EMMC_D2 (io), P20 FLASH_D0/EMMC_D0 (io), T18 FLASH_D1/EMMC_D1 (io), U19 FLASH_D6/EMMC_D6 (io), U22 GPIO4_B0/FLASH_CS1 (io), V20 FLASH_D5/EMMC_D5 (io), V22 FLASH_RDN (out), W20 FLASH_D7/EMMC_D7 (io), W23 FLASH_CLE (out), Y23 FLASH_CS0 (out)
part L pins: K19 GPIO0_A7/I2S0_SDI (io), K20 GPIO0_B3/I2S0_LRCK_TX (io), L21 GPIO0_B5/I2S0_D1 (io), M21 GPIO0_B4/I2S0_D0 (io), P21 GPIO0_B2/I2S0_LRCK_RX (io), P22 GPIO0_B0/I2S0_CLK (io), P23 GPIO0_B1/I2S0_SCLK (io), T22 GPIO0_B6/I2S0_D2 (io), U21 GPIO0_B7/I2S0_D3 (io), U23 GPIO1_B2/SPDIF_TX (io)
part M pins: G22 GPIO2_D4/I2C0_SDA (io), H21 GPIO2_D5/I2C0_SCL (io), H23 GPIO0_D7/PWM3 (io), J21 GPIO0_A4/PWM1 (io), K21 GPIO0_D6/PWM2 (io), K22 GPIO0_A3/PWM0 (io), L22 GPIO3_D6/UART3_RTS (io), L23 GPIO3_D5/UART3_CTS (io), M22 GPIO3_D4/UART3_SOUT (io), N22 GPIO3_D3/UART3_SIN (io), N23 GPIO3_A1/I2C2_SCL (io), R22 GPIO2_D7/I2C1_SCL (io), T19 GPIO1_B0/UART2_SIN (io), T21 GPIO2_D6/I2C1_SDA (io), T23 GPIO1_B1/UART2_SOUT (io), U20 GPIO3_A0/I2C2_SDA (io)
part N pins: A7 DDR_D27 (io), A8 DDR_DQS3n (out), A10 DDR_D31 (io), A11 DDR_DQS1n (out), A13 DDR_D14 (io), A14 DDR_WEn (out), A16 DDR_CLKn (out), A17 DDR_A5 (out), A19 DDR_A8 (out), A20 DDR_A9 (out), A22 DDR_DQS2n (out), A23 DDR_A10 (out), B7 DDR_D26 (io), B8 DDR_DQS3 (out), B9 DDR_D29 (io), B10 DDR_DM1 (out), B11 DDR_DQS1 (out), B12 DDR_D13 (io), B13 DDR_D15 (io), B14 DDR_CS0 (out), B15 DDR_CASn (out), B16 DDR_CLK (out), B17 DDR_A6 (out), B18 DDR_A7 (out), B19 DDR_A11 (out), B20 DDR_A13 (out), B21 DDR_A12 (out), B22 DDR_DQS2 (out), B23 DDR_D17 (io), C7 DDR_D24 (io), C8 DDR_D25 (io), C9 DDR_D30 (io), C10 DDR_D8 (io), C11 DDR_D12 (io), C12 DDR_RASn (out), C13 DDR_CKE0 (out), C14 DDR_A0 (out), C15 DDR_A2 (out), C17 DDR_A3 (out), C18 DDR_ODT1 (out), C19 DDR_ODT0 (out), C20 DDR_A14 (out), C21 DDR_D20 (io), C22 DDR_D16 (io), D7 DDR_DM3 (out), D8 DDR_D9 (io), D10 DDR_D11 (io), D11 DDR_BA0 (out), D13 DDR_BA2 (out), D14 DDR_A1 (out), D16 DDR_DM2 (out), D17 DDR_D18 (io), D18 DDR_D19 (io), D19 DDR_D21 (io), D21 DDR_D22 (io), D22 DDR_DM0 (out), D23 DDR_D0 (io), E7 DDR_D28 (io), E8 DDR_D10 (io), E10 DDR_CKE1 (out), E11 DDR_BA1 (out), E13 DDR_RESET (out), E14 DDR_CS1 (out), E16 DDR_A4 (out), E17 DDR_D23 (io), E18 DDR_D3 (io), E20 DDR_D7 (io), E21 DDR_D4 (io), E22 DDR_DQS0 (out), E23 DDR_DQS0n (out), F10 MVDD1 (power), F11 MVDD2 (power), F13 DDR_VREF (power), F14 MVDD3 (power), F16 MVDD4 (power), F17 MVDD5 (power), F19 DDR_D1 (io), F20 DDR_D2 (io), F21 DDR_D6 (io), F22 DDR_D5 (io), G10 MVDD6 (power), G13 MVDD7 (power), G14 MVDD8 (power), G15 DDR_PZQ (in)
part O pins: A1 HDMI_TX2 (out), A2 HDMI_TX1 (out), A4 HDMI_TX0 (out), A5 HDM I_TXC (out), B1 HDMI_TX2n (out), B2 HDMI_TX1n (out), B3 HDMIAVSS1 (power), B4 HDMI_TX0n (out), B5 HDM I_TXCn (out), B6 HDMIAVSS2 (power), C5 HDMIAVSS3 (power), C6 HDM I_REXT (out), F7 VDD11_HDMI (power), F8 VDD25_HDMI (power), G8 HDMIAVSS4 (power), G9 HDMIAVSS5 (power), G19 GPIO0_A1/HDMI_I2C_SCL (io), H19 GPIO0_A2/HDMI_I2C_SDA (io), K23 GPIO0_A0/HDMI_HOT_PLUG_IN (io)
part P pins: G11 CVDD1 (power), G16 CVDD2 (power), H7 CVDD3 (power), H17 VCCIO2 (power), J17 CVDD4 (power), K17 VCCIO1 (power), L17 CVDD5 (power), N5 AVDD1 (power), N7 CVDD6 (power), P5 AVDD2 (power), P6 AVDD3 (power), P17 CVDD7 (power), T5 AVDD4 (power), T6 AVDD5 (power), T17 CVDD8 (power), U5 AVDD6 (power), U6 AVDD7 (power), U8 AVDD9 (power), U9 AVDD10 (power), V5 AVDD8 (power), V7 AVDD11 (power), V8 AVDD12 (power), V10 AVDD_COM (out)
part Q pins: AA16 VSS86 (power), AA17 VSS87 (power), AB10 VSS88 (power), C16 VSS1 (power), D20 VSS2 (power), G12 VSS3 (power), H8 VSS4 (power), H9 VSS5 (power), H10 VSS6 (power), H11 VSS7 (power), H12 VSS8 (power), H13 VSS9 (power), H14 VSS10 (power), H15 VSS11 (power), H16 VSS12 (power), J8 VSS13 (power), J9 VSS14 (power), J10 VSS15 (power), J11 VSS16 (power), J12 VSS17 (power), J13 VSS18 (power), J14 VSS19 (power), J15 VSS20 (power), J16 VSS21 (power), K8 VSS22 (power), K9 VSS23 (power), K10 VSS24 (power), K11 VSS25 (power), K12 VSS26 (power), K13 VSS27 (power), K14 VSS28 (power), K15 VSS29 (power), K16 VSS30 (power), L8 VSS31 (power), L9 VSS32 (power), L10 VSS33 (power), L11 VSS34 (power), L12 VSS35 (power), L13 VSS36 (power), L14 VSS37 (power), L15 VSS38 (power), L16 VSS39 (power), M8 VSS40 (power), M9 VSS41 (power), M10 VSS42 (power), M11 VSS43 (power), M12 VSS44 (power), M13 VSS45 (power), M14 VSS46 (power), M15 VSS47 (power), M16 VSS48 (power), M17 VSS49 (power), N8 VSS50 (power), N9 VSS51 (power), N10 VSS52 (power), N11 VSS53 (power), N12 VSS54 (power), N13 VSS55 (power), N14 VSS56 (power), N15 VSS57 (power), N16 VSS58 (power), P7 VSS59 (power), P8 VSS60 (power), P9 VSS61 (power), P10 VSS62 (power), P11 VSS63 (power), P12 VSS64 (power), P13 VSS65 (power), P14 VSS66 (power), P15 VSS67 (power), P16 VSS68 (power), R7 VSS69 (power), R8 VSS70 (power), R9 VSS71 (power), R10 VSS72 (power), R11 VSS73 (power), R12 VSS74 (power), R13 VSS75 (power), R14 VSS76 (power), R15 VSS77 (power), R16 VSS78 (power), T7 VSS79 (power), T8 VSS80 (power), T9 VSS81 (power), T10 VSS82 (power), T14 VSS83 (power), T15 VSS84 (power), T16 VSS85 (power)

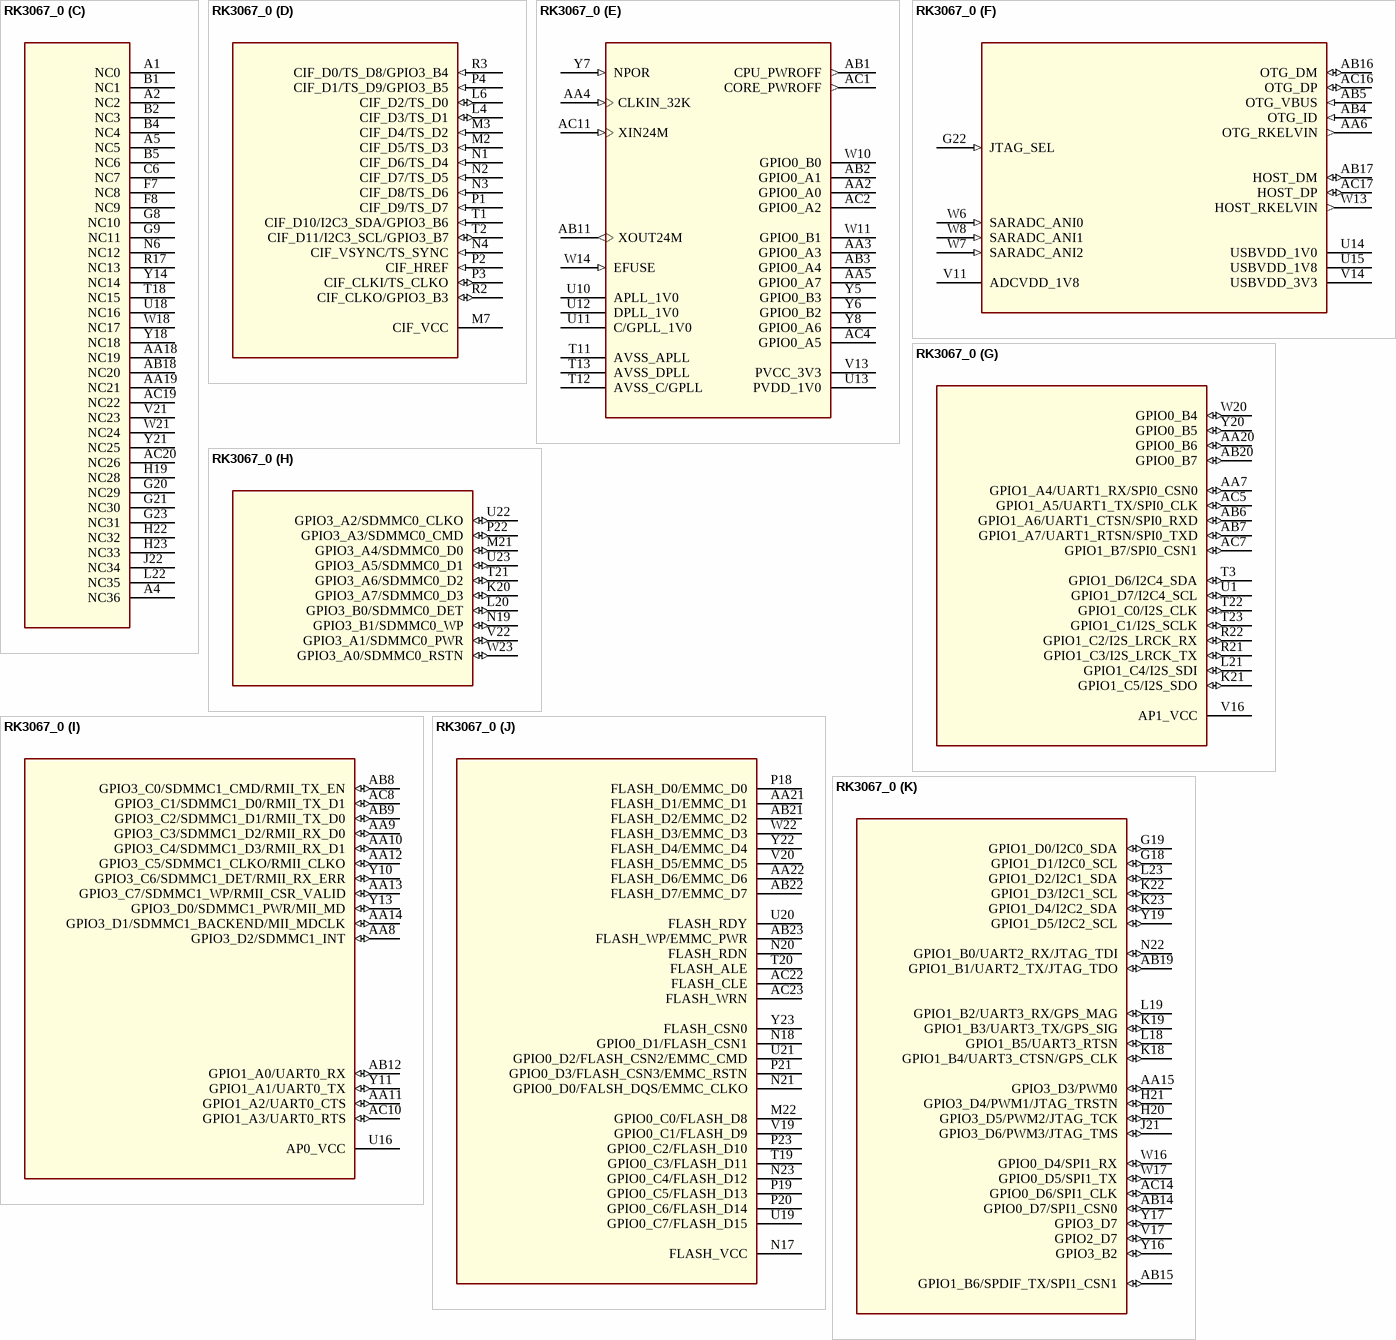
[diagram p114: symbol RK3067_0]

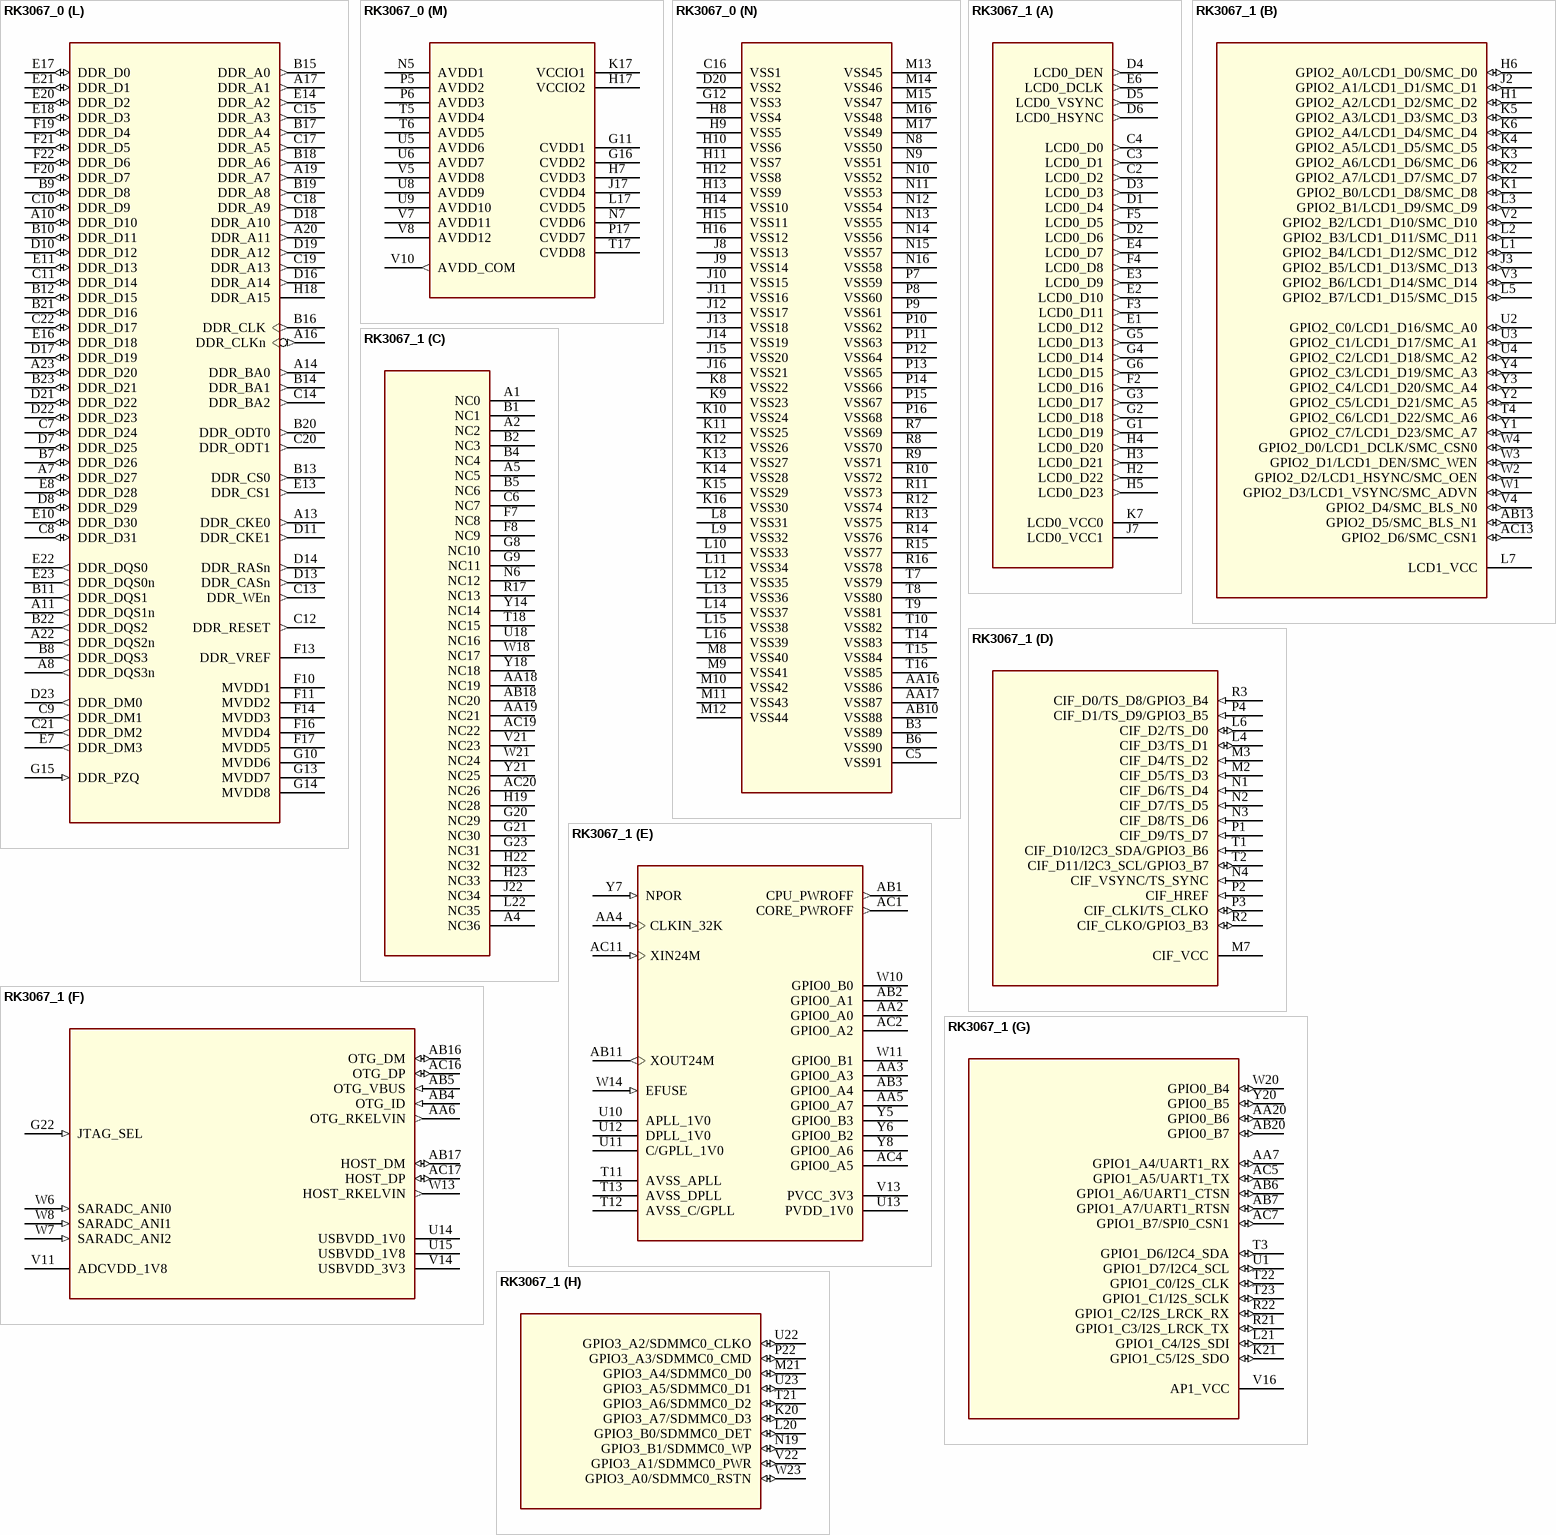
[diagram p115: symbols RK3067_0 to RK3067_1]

## RK3067_0
designator U?
Altium-Right: 180; Altium-Bottom: 370; Altium-Right1: 70; Altium-Bottom1: 390; Altium-Right2: 150; Altium-Bottom2: 210; Altium-Bottom3: 250; Altium-Right4: 230; Altium-Bottom5: 240; Altium-Right6: 160; Altium-Bottom6: 130; Altium-Right7: 220; Altium-Bottom7: 280; Altium-Right8: 200; Altium-Bottom8: 350; Altium-Bottom9: 330; Altium-Right10: 140; Altium-Bottom10: 520; Altium-Right11: 110; Altium-Bottom11: 170; Altium-Right12: 100; Altium-Bottom12: 500; Altium-Right13: 80
footprint BGA453-19X19
part A pins: C2 LCD0_D2 (out), C3 LCD0_D1 (out), C4 LCD0_D0 (out), D1 LCD0_D4 (out), D2 LCD0_D6 (out), D3 LCD0_D3 (out), D4 LCD0_DEN (out), D5 LCD0_VSYNC (out), D6 LCD0_HSYNC (out), E1 LCD0_D12 (out), E2 LCD0_D10 (out), E3 LCD0_D9 (out), E4 LCD0_D7 (out), E6 LCD0_DCLK (out), F2 LCD0_D16 (out), F3 LCD0_D11 (out), F4 LCD0_D8 (out), F5 LCD0_D5 (out), G1 LCD0_D19 (out), G2 LCD0_D18 (out), G3 LCD0_D17 (out), G4 LCD0_D14 (out), G5 LCD0_D13 (out), G6 LCD0_D15 (out), H2 LCD0_D22 (out), H3 LCD0_D21 (out), H4 LCD0_D20 (out), H5 LCD0_D23 (out), J7 LCD0_VCC1 (power), K7 LCD0_VCC0 (power)
part B pins: AB13 GPIO2_D5/SMC_BLS_N1 (io), AC13 GPIO2_D6/SMC_CSN1 (io), H1 GPIO2_A2/LCD1_D2/SMC_D2 (io), H6 GPIO2_A0/LCD1_D0/SMC_D0 (io), J2 GPIO2_A1/LCD1_D1/SMC_D1 (io), J3 GPIO2_B5/LCD1_D13/SMC_D13 (io), K1 GPIO2_B0/LCD1_D8/SMC_D8 (io), K2 GPIO2_A7/LCD1_D7/SMC_D7 (io), K3 GPIO2_A6/LCD1_D6/SMC_D6 (io), K4 GPIO2_A5/LCD1_D5/SMC_D5 (io), K5 GPIO2_A3/LCD1_D3/SMC_D3 (io), K6 GPIO2_A4/LCD1_D4/SMC_D4 (io), L1 GPIO2_B4/LCD1_D12/SMC_D12 (io), L2 GPIO2_B3/LCD1_D11/SMC_D11 (io), L3 GPIO2_B1/LCD1_D9/SMC_D9 (io), L5 GPIO2_B7/LCD1_D15/SMC_D15 (io), L7 LCD1_VCC (power), T4 GPIO2_C6/LCD1_D22/SMC_A6 (io), U2 GPIO2_C0/LCD1_D16/SMC_A0 (io), U3 GPIO2_C1/LCD1_D17/SMC_A1 (io), U4 GPIO2_C2/LCD1_D18/SMC_A2 (io), V2 GPIO2_B2/LCD1_D10/SMC_D10 (io), V3 GPIO2_B6/LCD1_D14/SMC_D14 (io), V4 GPIO2_D4/SMC_BLS_N0 (io), W1 GPIO2_D3/LCD1_VSYNC/SMC_ADVN (io), W2 GPIO2_D2/LCD1_HSYNC/SMC_OEN (io), W3 GPIO2_D1/LCD1_DEN/SMC_WEN (io), W4 GPIO2_D0/LCD1_DCLK/SMC_CSN0 (io), Y1 GPIO2_C7/LCD1_D23/SMC_A7 (io), Y2 GPIO2_C5/LCD1_D21/SMC_A5 (io), Y3 GPIO2_C4/LCD1_D20/SMC_A4 (io), Y4 GPIO2_C3/LCD1_D19/SMC_A3 (io)
part C pins: A1 NC0, A2 NC2, A4 NC36, A5 NC5, AA18 NC19, AA19 NC21, AB18 NC20, AC19 NC22, AC20 NC26, B1 NC1, B2 NC3, B4 NC4, B5 NC6, C6 NC7, F7 NC8, F8 NC9, G8 NC10, G9 NC11, G20 NC29, G21 NC30, G23 NC31, H19 NC28, H22 NC32, H23 NC33, J22 NC34, L22 NC35, N6 NC12, R17 NC13, T18 NC15, U18 NC16, V21 NC23, W18 NC17, W21 NC24, Y14 NC14, Y18 NC18, Y21 NC25
part D pins: L4 CIF_D3/TS_D1 (io), L6 CIF_D2/TS_D0 (io), M2 CIF_D5/TS_D3 (in), M3 CIF_D4/TS_D2 (in), M7 CIF_VCC (power), N1 CIF_D6/TS_D4 (in), N2 CIF_D7/TS_D5 (in), N3 CIF_D8/TS_D6 (in), N4 CIF_VSYNC/TS_SYNC (in), P1 CIF_D9/TS_D7 (in), P2 CIF_HREF (in), P3 CIF_CLKI/TS_CLKO (io), P4 CIF_D1/TS_D9/GPIO3_B5 (in), R2 CIF_CLKO/GPIO3_B3 (io), R3 CIF_D0/TS_D8/GPIO3_B4 (in), T1 CIF_D10/I2C3_SDA/GPIO3_B6 (in), T2 CIF_D11/I2C3_SCL/GPIO3_B7 (io)
part E pins: AA2 GPIO0_A0, AA3 GPIO0_A3, AA4 CLKIN_32K (in), AA5 GPIO0_A7, AB1 CPU_PWROFF (out), AB2 GPIO0_A1, AB3 GPIO0_A4, AB11 XOUT24M (out), AC1 CORE_PWROFF (out), AC2 GPIO0_A2, AC4 GPIO0_A5, AC11 XIN24M (in), T11 AVSS_APLL (power), T12 AVSS_C/GPLL (power), T13 AVSS_DPLL (power), U10 APLL_1V0 (power), U11 C/GPLL_1V0 (power), U12 DPLL_1V0 (power), U13 PVDD_1V0 (power), V13 PVCC_3V3 (power), W10 GPIO0_B0, W11 GPIO0_B1, W14 EFUSE (in), Y5 GPIO0_B3, Y6 GPIO0_B2, Y7 NPOR (in), Y8 GPIO0_A6
part F pins: AA6 OTG_RKELVIN (out), AB4 OTG_ID (in), AB5 OTG_VBUS (in), AB16 OTG_DM (io), AB17 HOST_DM (io), AC16 OTG_DP (io), AC17 HOST_DP (io), G22 JTAG_SEL (in), U14 USBVDD_1V0 (power), U15 USBVDD_1V8 (power), V11 ADCVDD_1V8 (power), V14 USBVDD_3V3 (power), W6 SARADC_ANI0 (in), W7 SARADC_ANI2 (in), W8 SARADC_ANI1 (in), W13 HOST_RKELVIN (out)
part G pins: AA7 GPIO1_A4/UART1_RX/SPI0_CSN0 (io), AA20 GPIO0_B6 (io), AB6 GPIO1_A6/UART1_CTSN/SPI0_RXD (io), AB7 GPIO1_A7/UART1_RTSN/SPI0_TXD (io), AB20 GPIO0_B7 (io), AC5 GPIO1_A5/UART1_TX/SPI0_CLK (io), AC7 GPIO1_B7/SPI0_CSN1 (io), K21 GPIO1_C5/I2S_SDO (io), L21 GPIO1_C4/I2S_SDI (io), R21 GPIO1_C3/I2S_LRCK_TX (io), R22 GPIO1_C2/I2S_LRCK_RX (io), T3 GPIO1_D6/I2C4_SDA (io), T22 GPIO1_C0/I2S_CLK (io), T23 GPIO1_C1/I2S_SCLK (io), U1 GPIO1_D7/I2C4_SCL (io), V16 AP1_VCC (power), W20 GPIO0_B4 (io), Y20 GPIO0_B5 (io)
part H pins: K20 GPIO3_A7/SDMMC0_D3 (io), L20 GPIO3_B0/SDMMC0_DET (io), M21 GPIO3_A4/SDMMC0_D0 (io), N19 GPIO3_B1/SDMMC0_WP (io), P22 GPIO3_A3/SDMMC0_CMD (io), T21 GPIO3_A6/SDMMC0_D2 (io), U22 GPIO3_A2/SDMMC0_CLKO (io), U23 GPIO3_A5/SDMMC0_D1 (io), V22 GPIO3_A1/SDMMC0_PWR (io), W23 GPIO3_A0/SDMMC0_RSTN (io)
part I pins: AA8 GPIO3_D2/SDMMC1_INT (io), AA9 GPIO3_C3/SDMMC1_D2/RMII_RX_D0 (io), AA10 GPIO3_C4/SDMMC1_D3/RMII_RX_D1 (io), AA11 GPIO1_A2/UART0_CTS (io), AA12 GPIO3_C5/SDMMC1_CLKO/RMII_CLKO (io), AA13 GPIO3_C7/SDMMC1_WP/RMII_CSR_VALID (io), AA14 GPIO3_D1/SDMMC1_BACKEND/MII_MDCLK (io), AB8 GPIO3_C0/SDMMC1_CMD/RMII_TX_EN (io), AB9 GPIO3_C2/SDMMC1_D1/RMII_TX_D0 (io), AB12 GPIO1_A0/UART0_RX (io), AC8 GPIO3_C1/SDMMC1_D0/RMII_TX_D1 (io), AC10 GPIO1_A3/UART0_RTS (io), U16 AP0_VCC (power), Y10 GPIO3_C6/SDMMC1_DET/RMII_RX_ERR (io), Y11 GPIO1_A1/UART0_TX (io), Y13 GPIO3_D0/SDMMC1_PWR/MII_MD (io)
part J pins: AA21 FLASH_D1/EMMC_D1, AA22 FLASH_D6/EMMC_D6, AB21 FLASH_D2/EMMC_D2, AB22 FLASH_D7/EMMC_D7, AB23 FLASH_WP/EMMC_PWR, AC22 FLASH_CLE, AC23 FLASH_WRN, M22 GPIO0_C0/FLASH_D8, N17 FLASH_VCC, N18 GPIO0_D1/FLASH_CSN1, N20 FLASH_RDN, N21 GPIO0_D0/FALSH_DQS/EMMC_CLKO, N23 GPIO0_C4/FLASH_D12, P18 FLASH_D0/EMMC_D0, P19 GPIO0_C5/FLASH_D13, P20 GPIO0_C6/FLASH_D14, P21 GPIO0_D3/FLASH_CSN3/EMMC_RSTN, P23 GPIO0_C2/FLASH_D10, T19 GPIO0_C3/FLASH_D11, T20 FLASH_ALE, U19 GPIO0_C7/FLASH_D15, U20 FLASH_RDY, U21 GPIO0_D2/FLASH_CSN2/EMMC_CMD, V19 GPIO0_C1/FLASH_D9, V20 FLASH_D5/EMMC_D5, W22 FLASH_D3/EMMC_D3, Y22 FLASH_D4/EMMC_D4, Y23 FLASH_CSN0
part K pins: AA15 GPIO3_D3/PWM0 (io), AB14 GPIO0_D7/SPI1_CSN0 (io), AB15 GPIO1_B6/SPDIF_TX/SPI1_CSN1 (io), AB19 GPIO1_B1/UART2_TX/JTAG_TDO (io), AC14 GPIO0_D6/SPI1_CLK (io), G18 GPIO1_D1/I2C0_SCL (io), G19 GPIO1_D0/I2C0_SDA (io), H20 GPIO3_D5/PWM2/JTAG_TCK (io), H21 GPIO3_D4/PWM1/JTAG_TRSTN (io), J21 GPIO3_D6/PWM3/JTAG_TMS (io), K18 GPIO1_B4/UART3_CTSN/GPS_CLK (io), K19 GPIO1_B3/UART3_TX/GPS_SIG (io), K22 GPIO1_D3/I2C1_SCL (io), K23 GPIO1_D4/I2C2_SDA (io), L18 GPIO1_B5/UART3_RTSN (io), L19 GPIO1_B2/UART3_RX/GPS_MAG (io), L23 GPIO1_D2/I2C1_SDA (io), N22 GPIO1_B0/UART2_RX/JTAG_TDI (io), V17 GPIO2_D7 (io), W16 GPIO0_D4/SPI1_RX (io), W17 GPIO0_D5/SPI1_TX (io), Y16 GPIO3_B2 (io), Y17 GPIO3_D7 (io), Y19 GPIO1_D5/I2C2_SCL (io)
part L pins: A7 DDR_D27 (io), A8 DDR_DQS3n (out), A10 DDR_D10 (io), A11 DDR_DQS1n (out), A13 DDR_CKE0 (out), A14 DDR_BA0 (out), A16 DDR_CLKn (out), A17 DDR_A1 (out), A19 DDR_A7 (out), A20 DDR_A11 (out), A22 DDR_DQS2n (out), A23 DDR_D20 (io), B7 DDR_D26 (io), B8 DDR_DQS3 (out), B9 DDR_D8 (io), B10 DDR_D11 (io), B11 DDR_DQS1 (out), B12 DDR_D15 (io), B13 DDR_CS0 (out), B14 DDR_BA1 (out), B15 DDR_A0 (out), B16 DDR_CLK (out), B17 DDR_A4 (out), B18 DDR_A6 (out), B19 DDR_A8 (out), B20 DDR_ODT0 (out), B21 DDR_D16 (io), B22 DDR_DQS2 (out), B23 DDR_D21 (io), C7 DDR_D24 (io), C8 DDR_D31 (io), C9 DDR_DM1 (out), C10 DDR_D9 (io), C11 DDR_D14 (io), C12 DDR_RESET (out), C13 DDR_WEn (out), C14 DDR_BA2 (out), C15 DDR_A3 (out), C17 DDR_A5 (out), C18 DDR_A9 (out), C19 DDR_A13 (out), C20 DDR_ODT1 (out), C21 DDR_DM2 (out), C22 DDR_D17 (io), D7 DDR_D25 (io), D8 DDR_D29 (io), D10 DDR_D12 (io), D11 DDR_CKE1 (out), D13 DDR_CASn (out), D14 DDR_RASn (out), D16 DDR_A14 (out), D17 DDR_D19 (io), D18 DDR_A10 (out), D19 DDR_A12 (out), D21 DDR_D22 (io), D22 DDR_D23 (io), D23 DDR_DM0 (out), E7 DDR_DM3 (out), E8 DDR_D28 (io), E10 DDR_D30 (io), E11 DDR_D13 (io), E13 DDR_CS1 (out), E14 DDR_A2 (out), E16 DDR_D18 (io), E17 DDR_D0 (io), E18 DDR_D3 (io), E20 DDR_D2 (io), E21 DDR_D1 (io), E22 DDR_DQS0 (out), E23 DDR_DQS0n (out), F10 MVDD1 (power), F11 MVDD2 (power), F13 DDR_VREF (power), F14 MVDD3 (power), F16 MVDD4 (power), F17 MVDD5 (power), F19 DDR_D4 (io), F20 DDR_D7 (io), F21 DDR_D5 (io), F22 DDR_D6 (io), G10 MVDD6 (power), G13 MVDD7 (power), G14 MVDD8 (power), G15 DDR_PZQ (in), H18 DDR_A15
part M pins: G11 CVDD1 (power), G16 CVDD2 (power), H7 CVDD3 (power), H17 VCCIO2 (power), J17 CVDD4 (power), K17 VCCIO1 (power), L17 CVDD5 (power), N5 AVDD1 (power), N7 CVDD6 (power), P5 AVDD2 (power), P6 AVDD3 (power), P17 CVDD7 (power), T5 AVDD4 (power), T6 AVDD5 (power), T17 CVDD8 (power), U5 AVDD6 (power), U6 AVDD7 (power), U8 AVDD9 (power), U9 AVDD10 (power), V5 AVDD8 (power), V7 AVDD11 (power), V8 AVDD12 (power), V10 AVDD_COM (out)
part N pins: AA16 VSS86 (power), AA17 VSS87 (power), AB10 VSS88 (power), B3 VSS89 (power), B6 VSS90 (power), C5 VSS91 (power), C16 VSS1 (power), D20 VSS2 (power), G12 VSS3 (power), H8 VSS4 (power), H9 VSS5 (power), H10 VSS6 (power), H11 VSS7 (power), H12 VSS8 (power), H13 VSS9 (power), H14 VSS10 (power), H15 VSS11 (power), H16 VSS12 (power), J8 VSS13 (power), J9 VSS14 (power), J10 VSS15 (power), J11 VSS16 (power), J12 VSS17 (power), J13 VSS18 (power), J14 VSS19 (power), J15 VSS20 (power), J16 VSS21 (power), K8 VSS22 (power), K9 VSS23 (power), K10 VSS24 (power), K11 VSS25 (power), K12 VSS26 (power), K13 VSS27 (power), K14 VSS28 (power), K15 VSS29 (power), K16 VSS30 (power), L8 VSS31 (power), L9 VSS32 (power), L10 VSS33 (power), L11 VSS34 (power), L12 VSS35 (power), L13 VSS36 (power), L14 VSS37 (power), L15 VSS38 (power), L16 VSS39 (power), M8 VSS40 (power), M9 VSS41 (power), M10 VSS42 (power), M11 VSS43 (power), M12 VSS44 (power), M13 VSS45 (power), M14 VSS46 (power), M15 VSS47 (power), M16 VSS48 (power), M17 VSS49 (power), N8 VSS50 (power), N9 VSS51 (power), N10 VSS52 (power), N11 VSS53 (power), N12 VSS54 (power), N13 VSS55 (power), N14 VSS56 (power), N15 VSS57 (power), N16 VSS58 (power), P7 VSS59 (power), P8 VSS60 (power), P9 VSS61 (power), P10 VSS62 (power), P11 VSS63 (power), P12 VSS64 (power), P13 VSS65 (power), P14 VSS66 (power), P15 VSS67 (power), P16 VSS68 (power), R7 VSS69 (power), R8 VSS70 (power), R9 VSS71 (power), R10 VSS72 (power), R11 VSS73 (power), R12 VSS74 (power), R13 VSS75 (power), R14 VSS76 (power), R15 VSS77 (power), R16 VSS78 (power), T7 VSS79 (power), T8 VSS80 (power), T9 VSS81 (power), T10 VSS82 (power), T14 VSS83 (power), T15 VSS84 (power), T16 VSS85 (power)

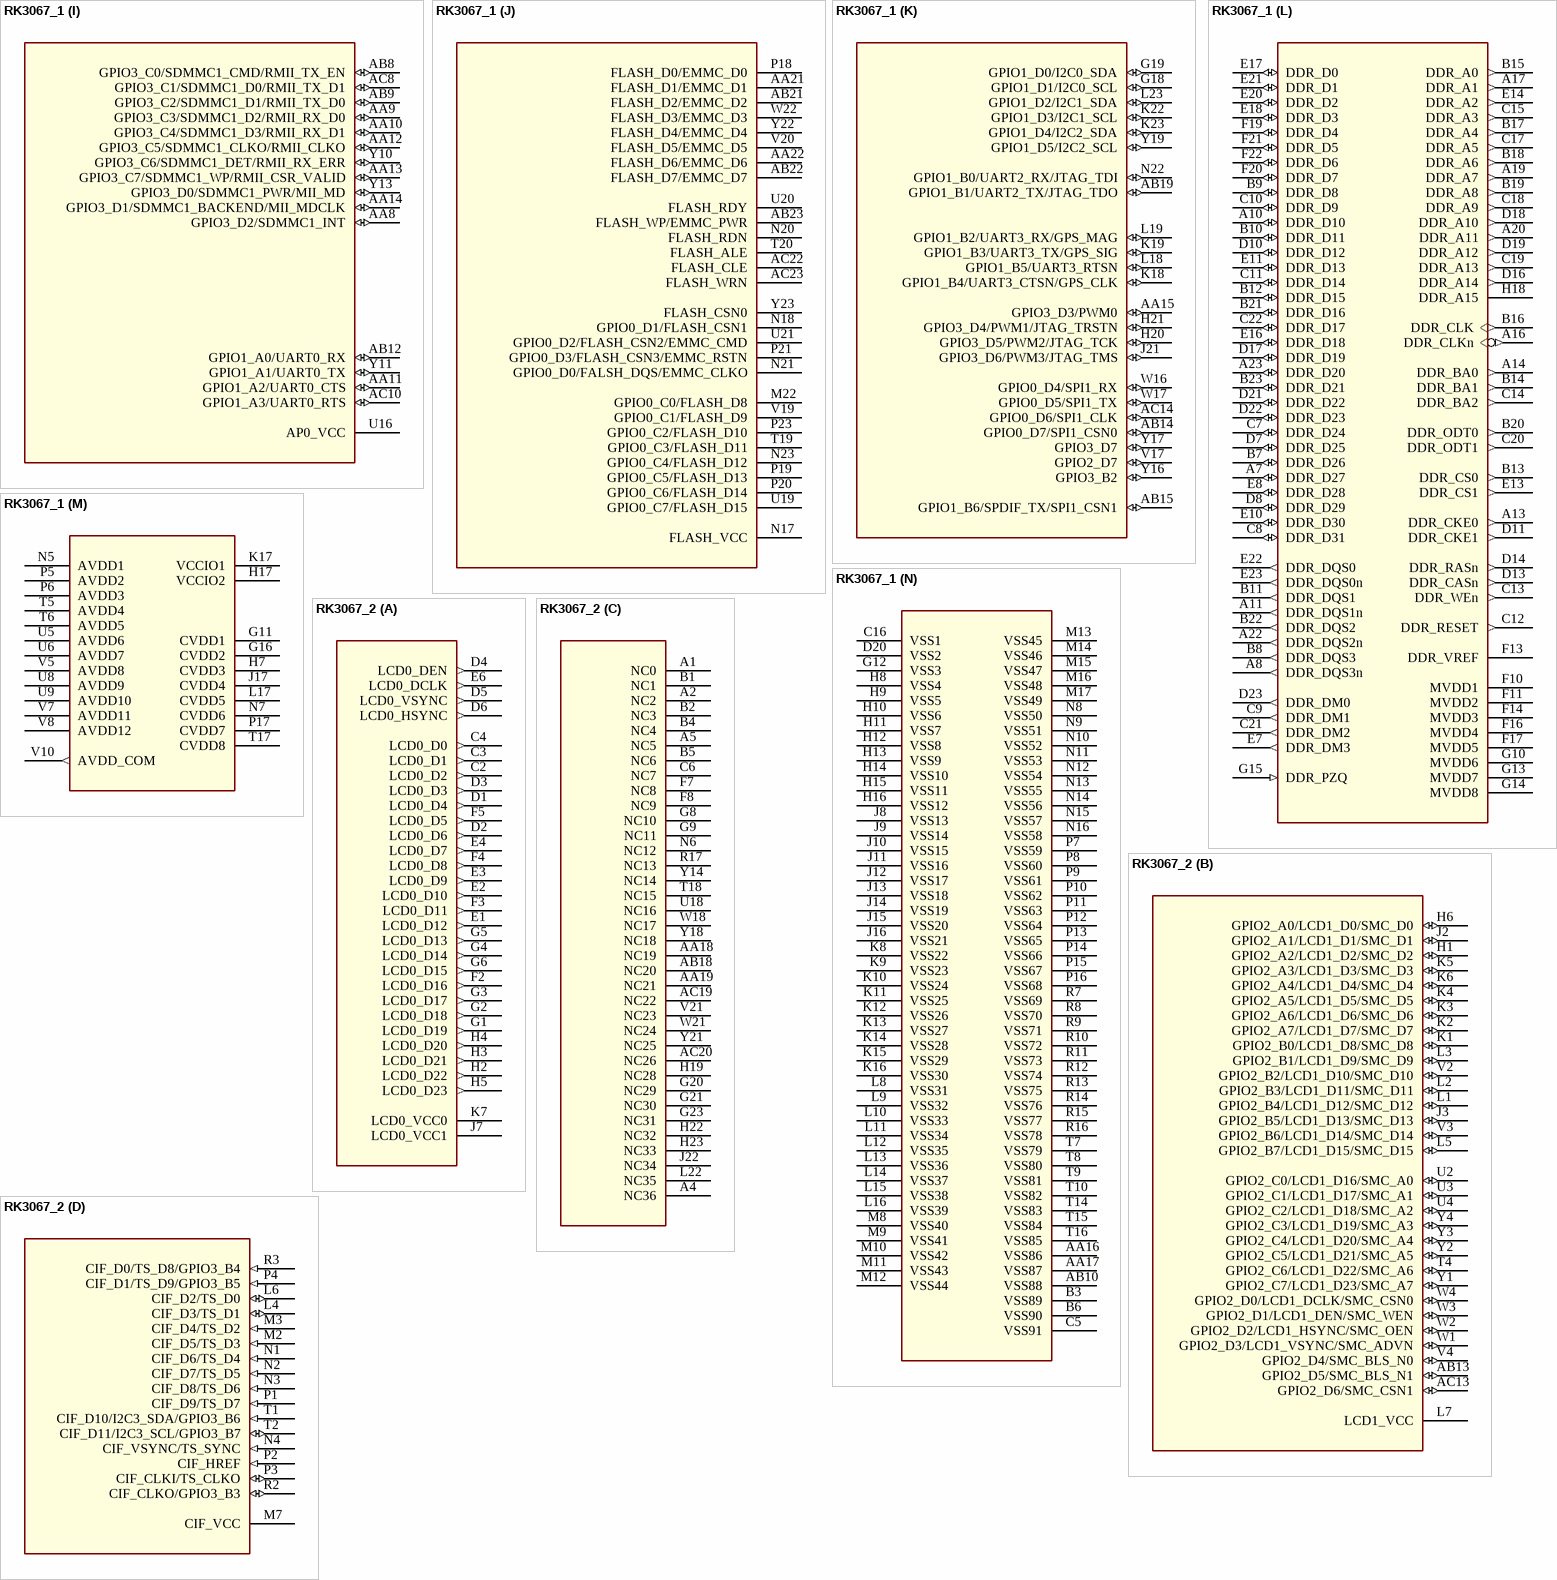
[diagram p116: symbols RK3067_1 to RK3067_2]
